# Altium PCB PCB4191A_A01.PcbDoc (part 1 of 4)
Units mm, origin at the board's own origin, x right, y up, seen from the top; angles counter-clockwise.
Board outline 160 x 160 mm, 6 copper layers (Top Layer, IM1 RIS, IM2 Signal, IM3 Signal, IM4 GND, Bottom Layer), stack 1.582 mm thick; 176 components, 121 nets, 494 pads, 4954 vias.
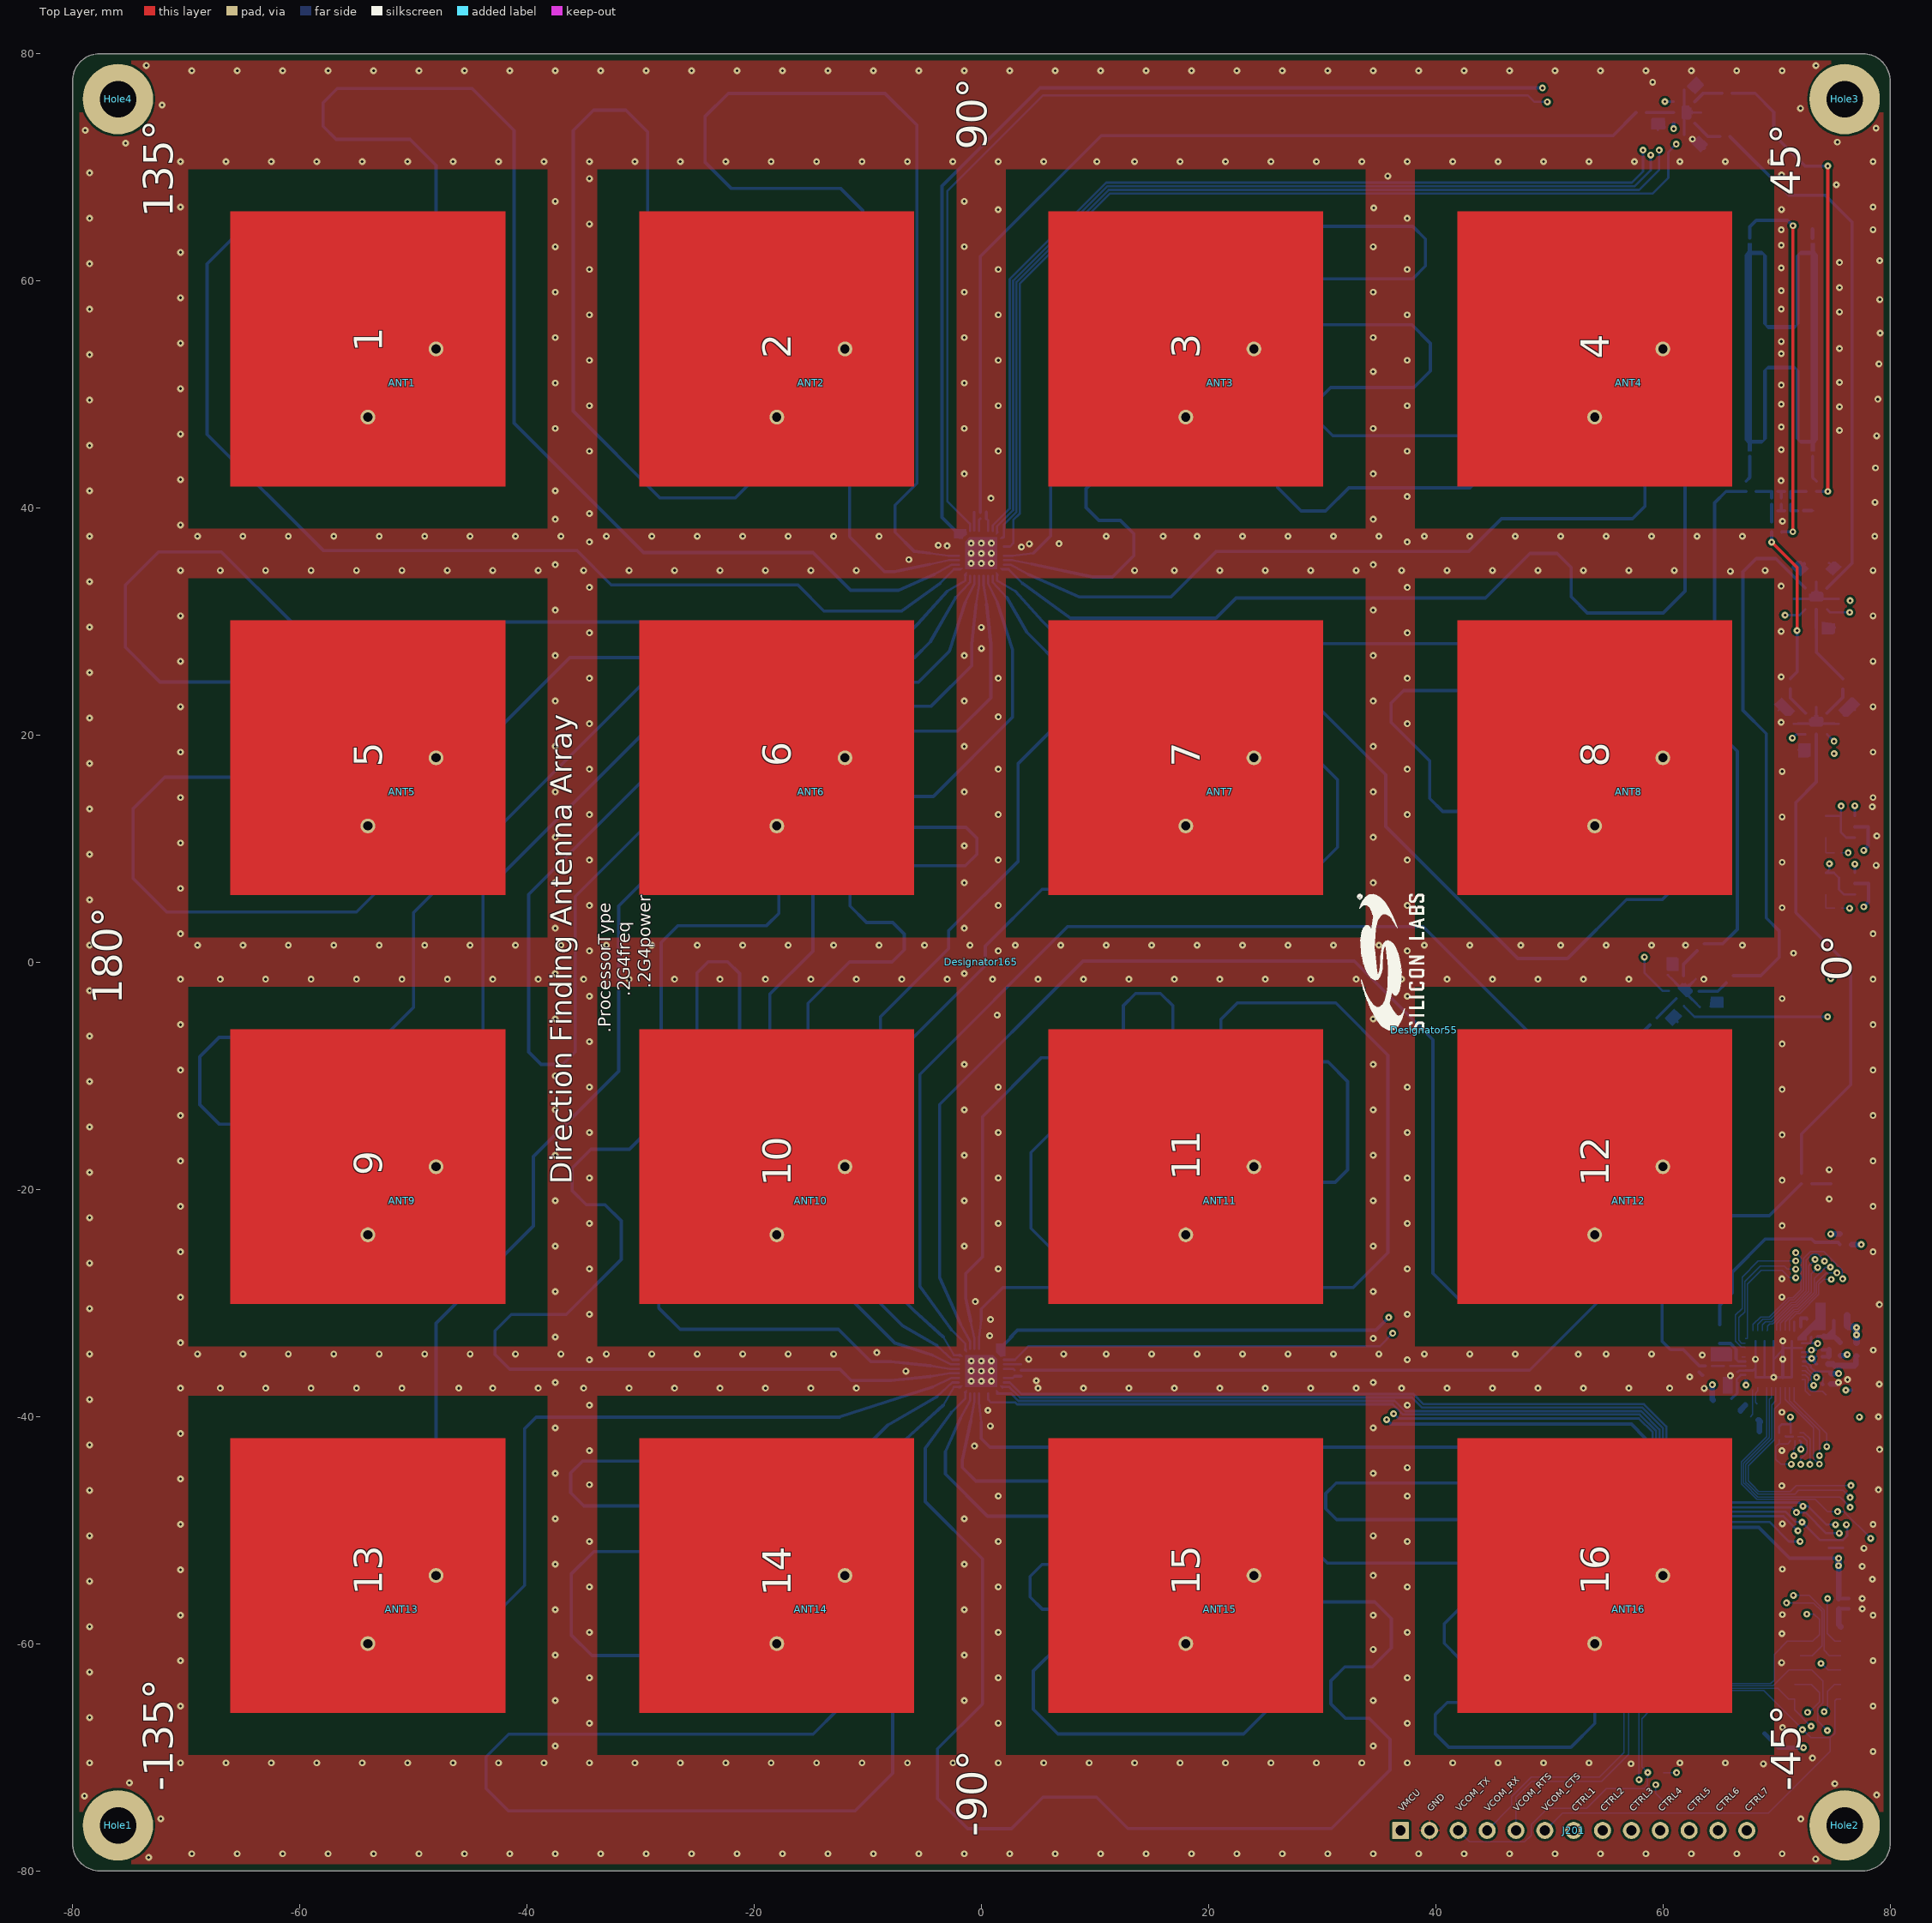
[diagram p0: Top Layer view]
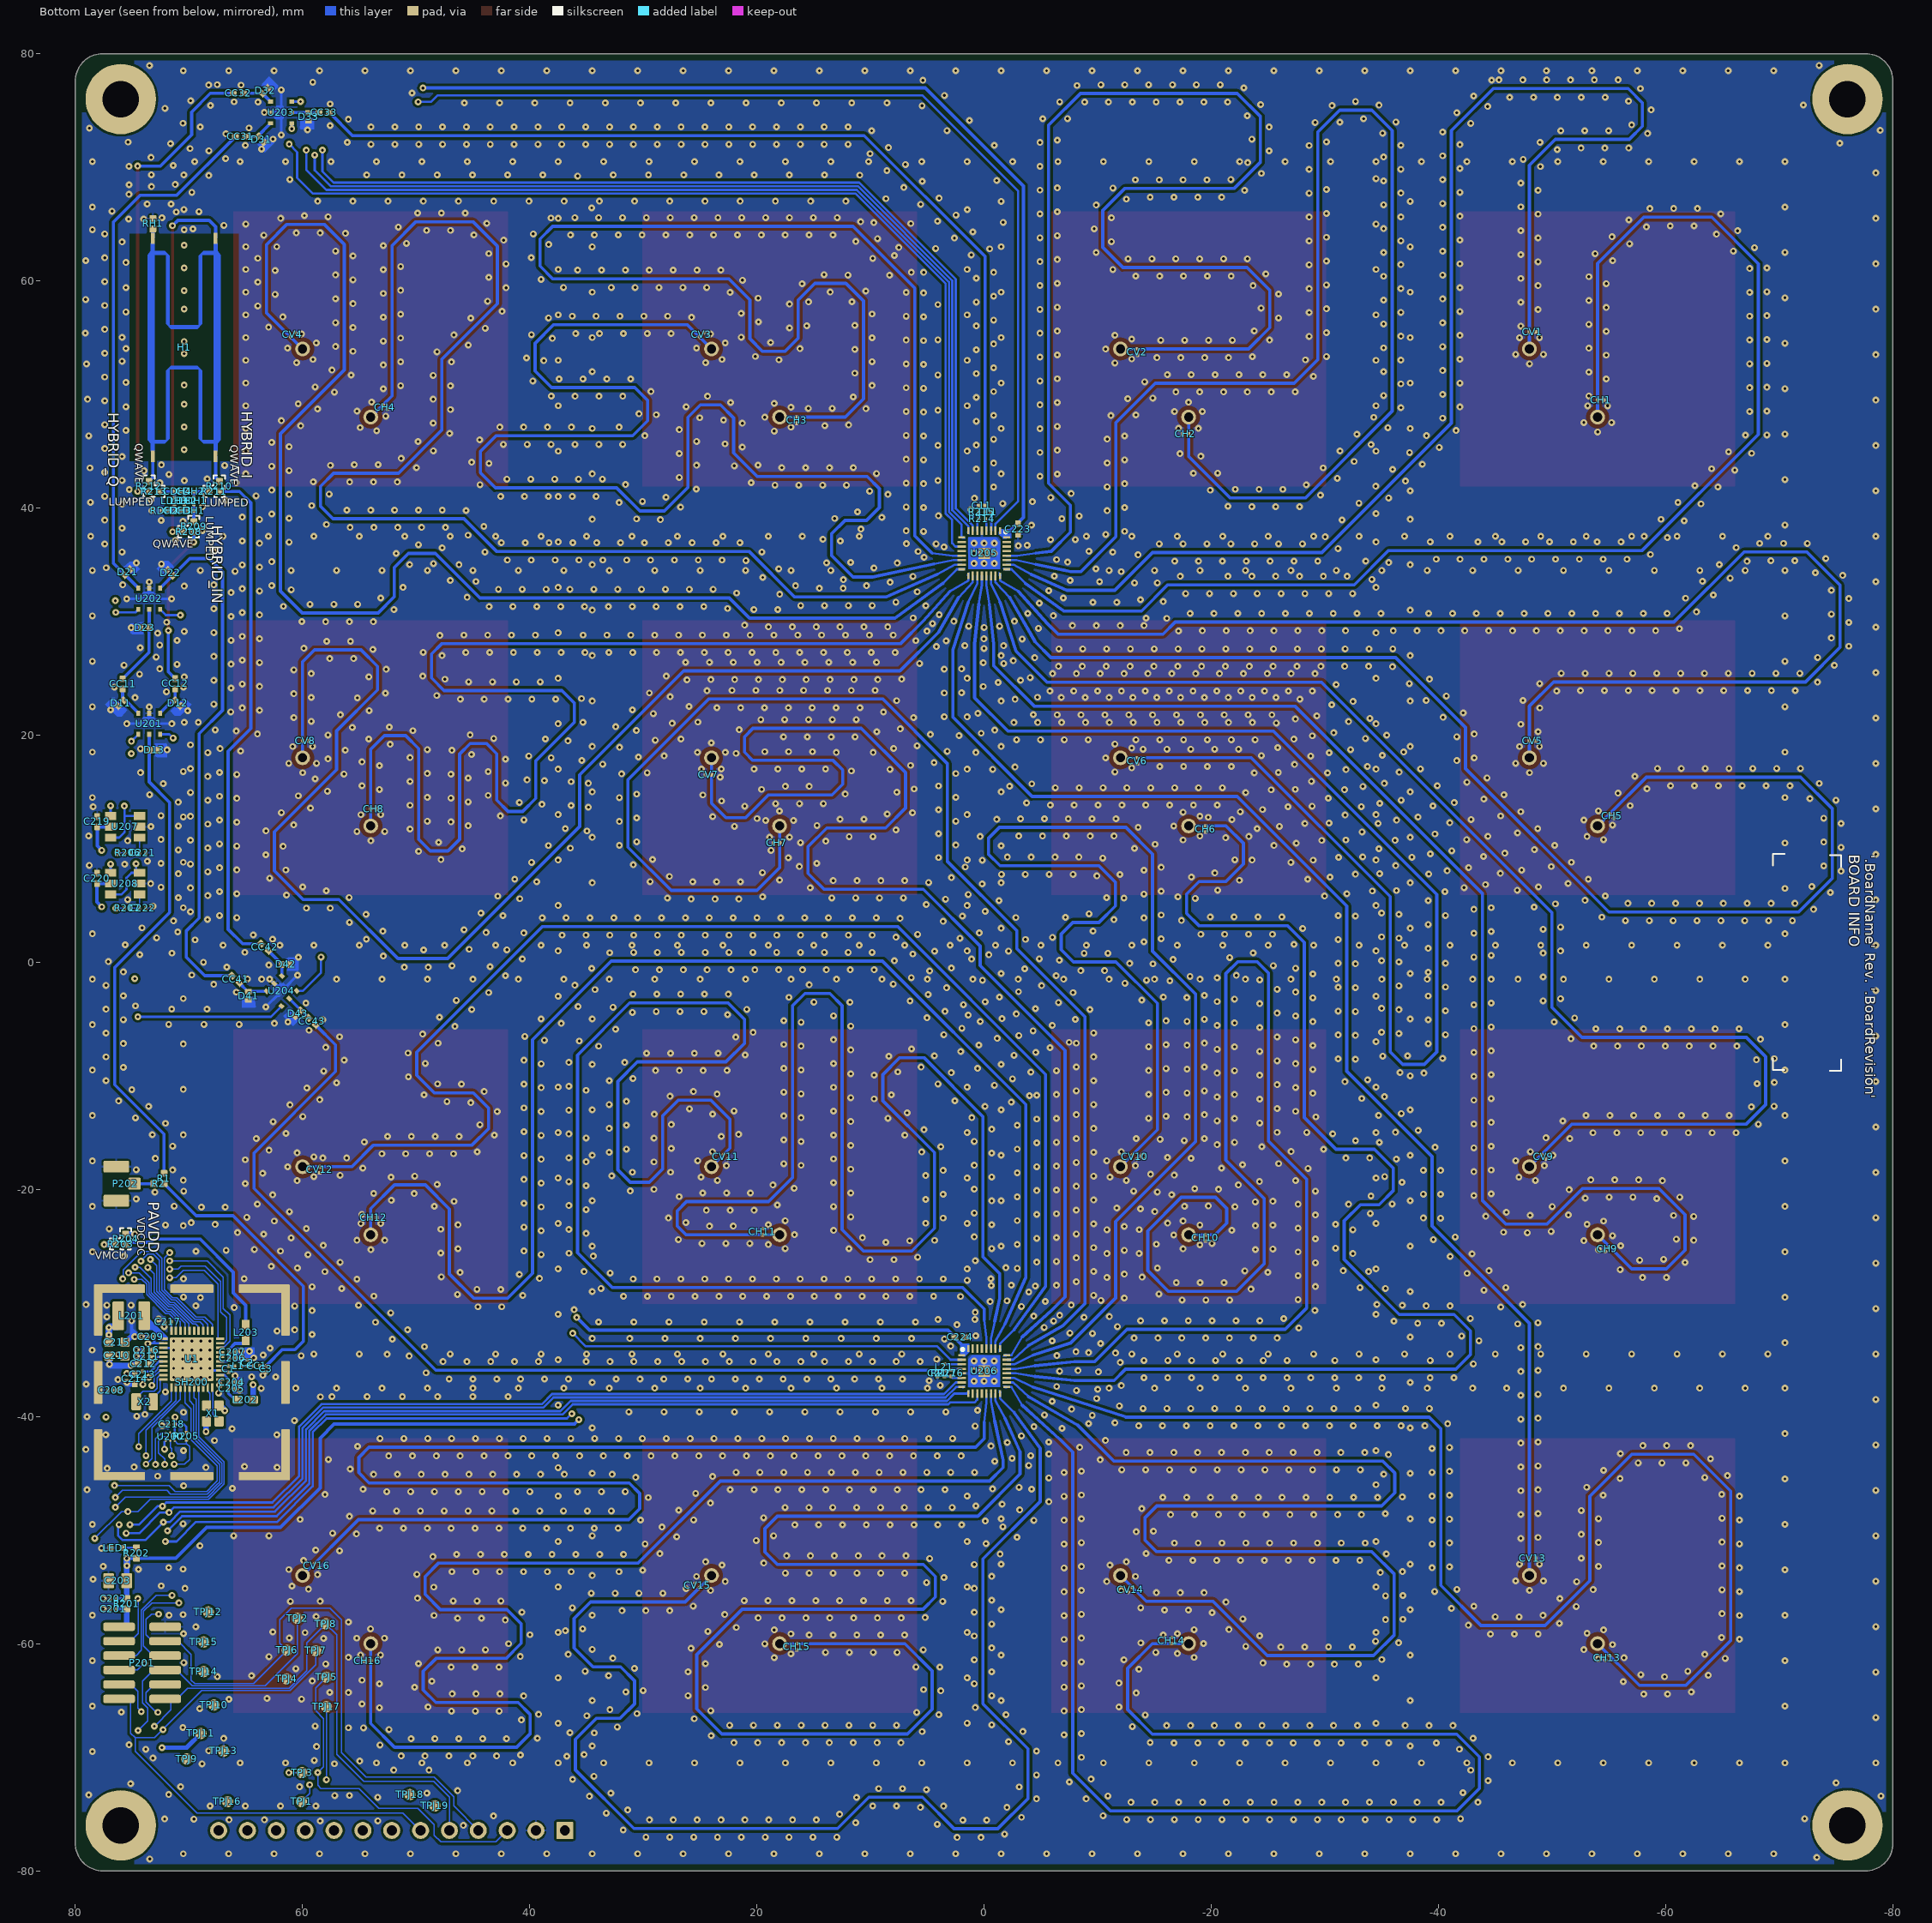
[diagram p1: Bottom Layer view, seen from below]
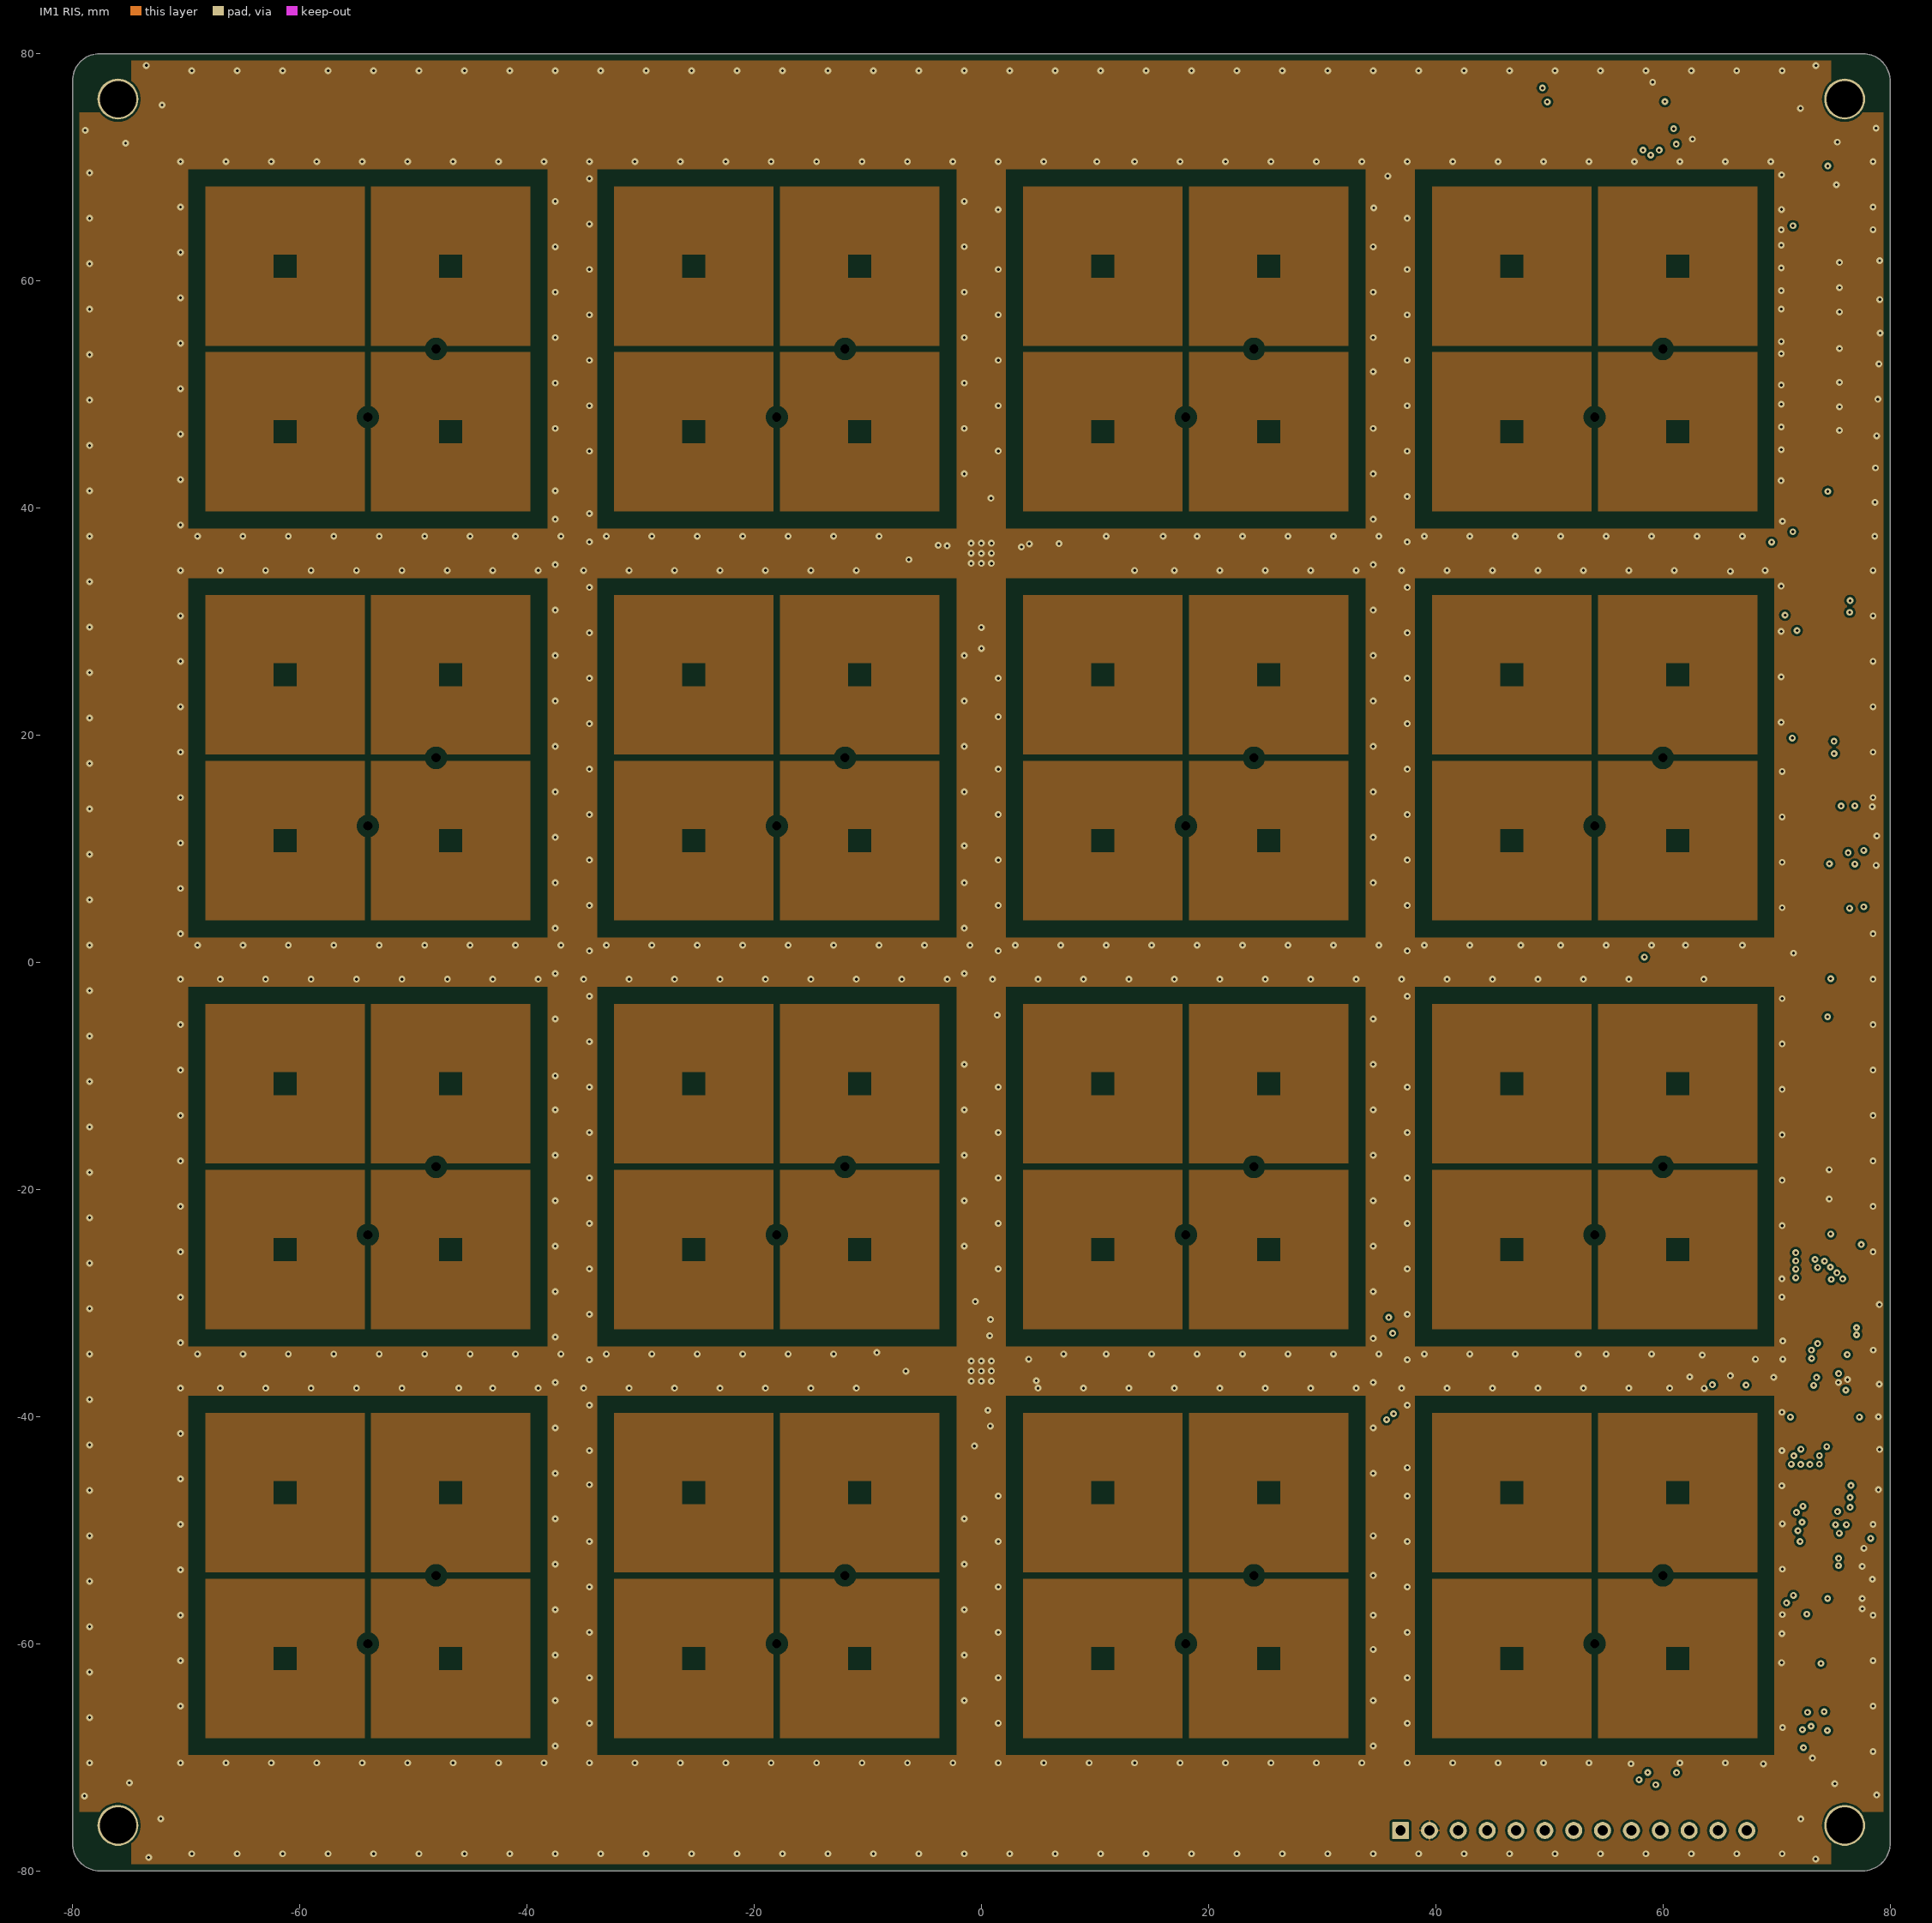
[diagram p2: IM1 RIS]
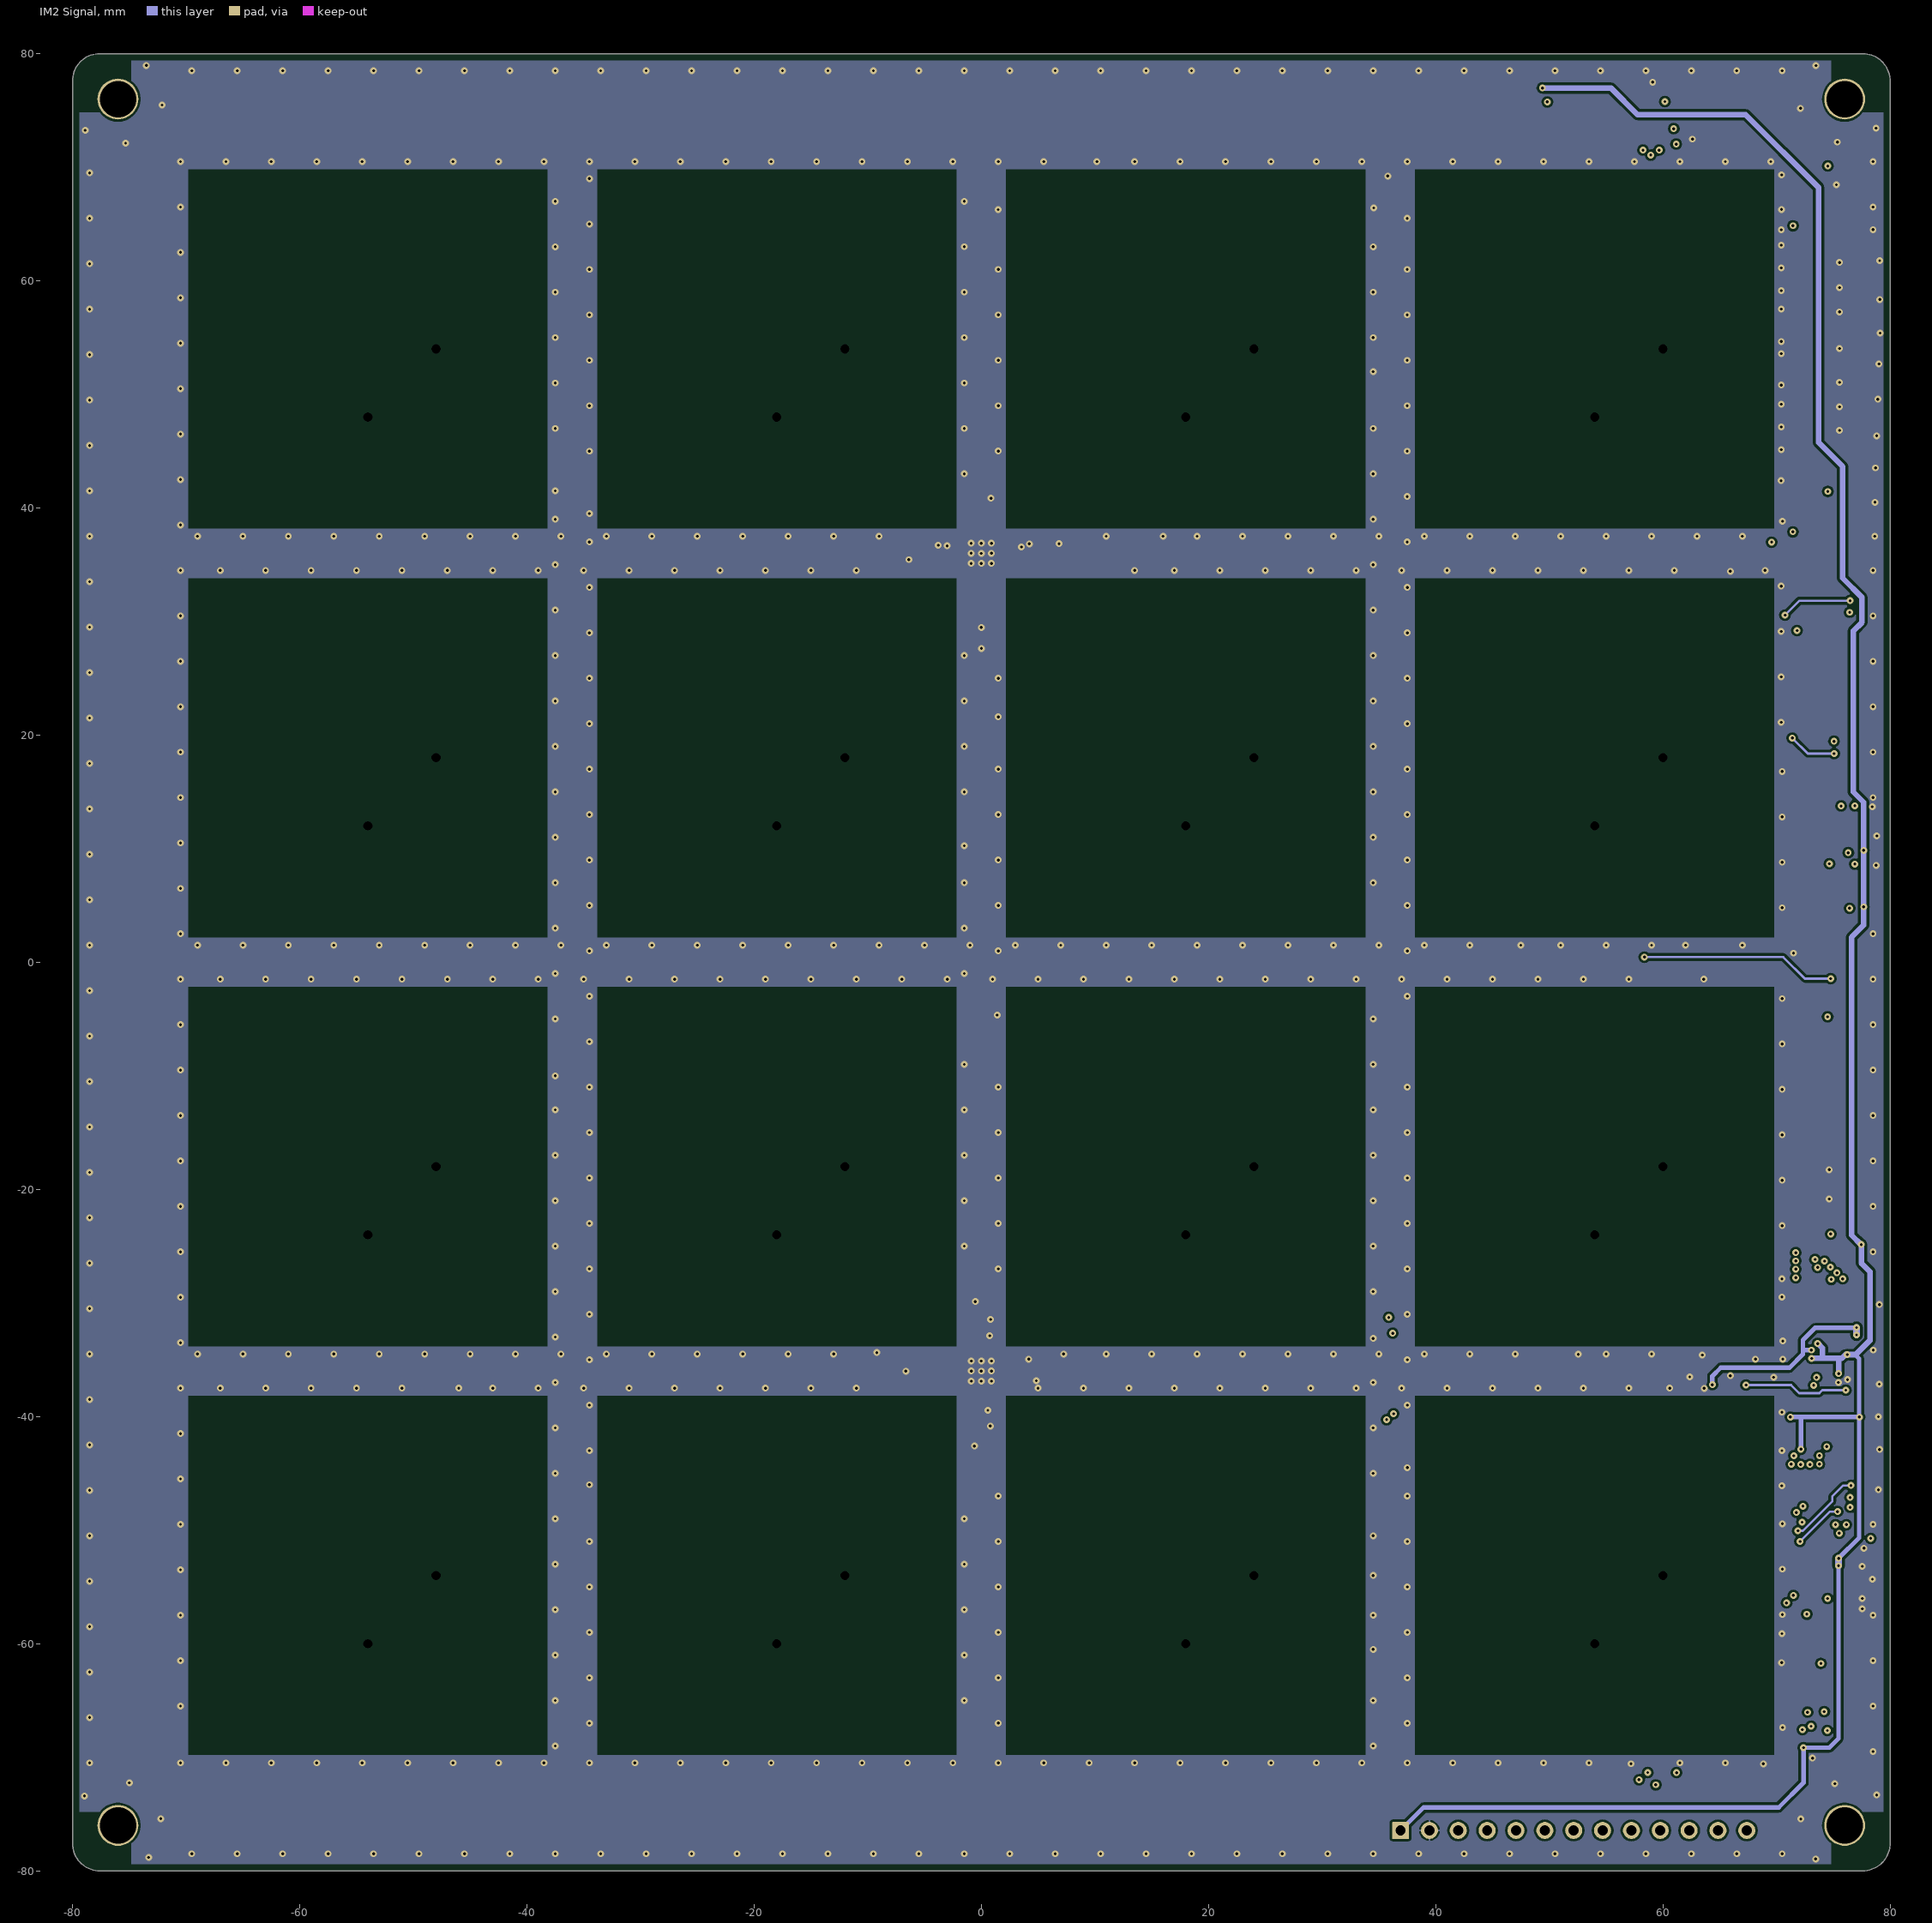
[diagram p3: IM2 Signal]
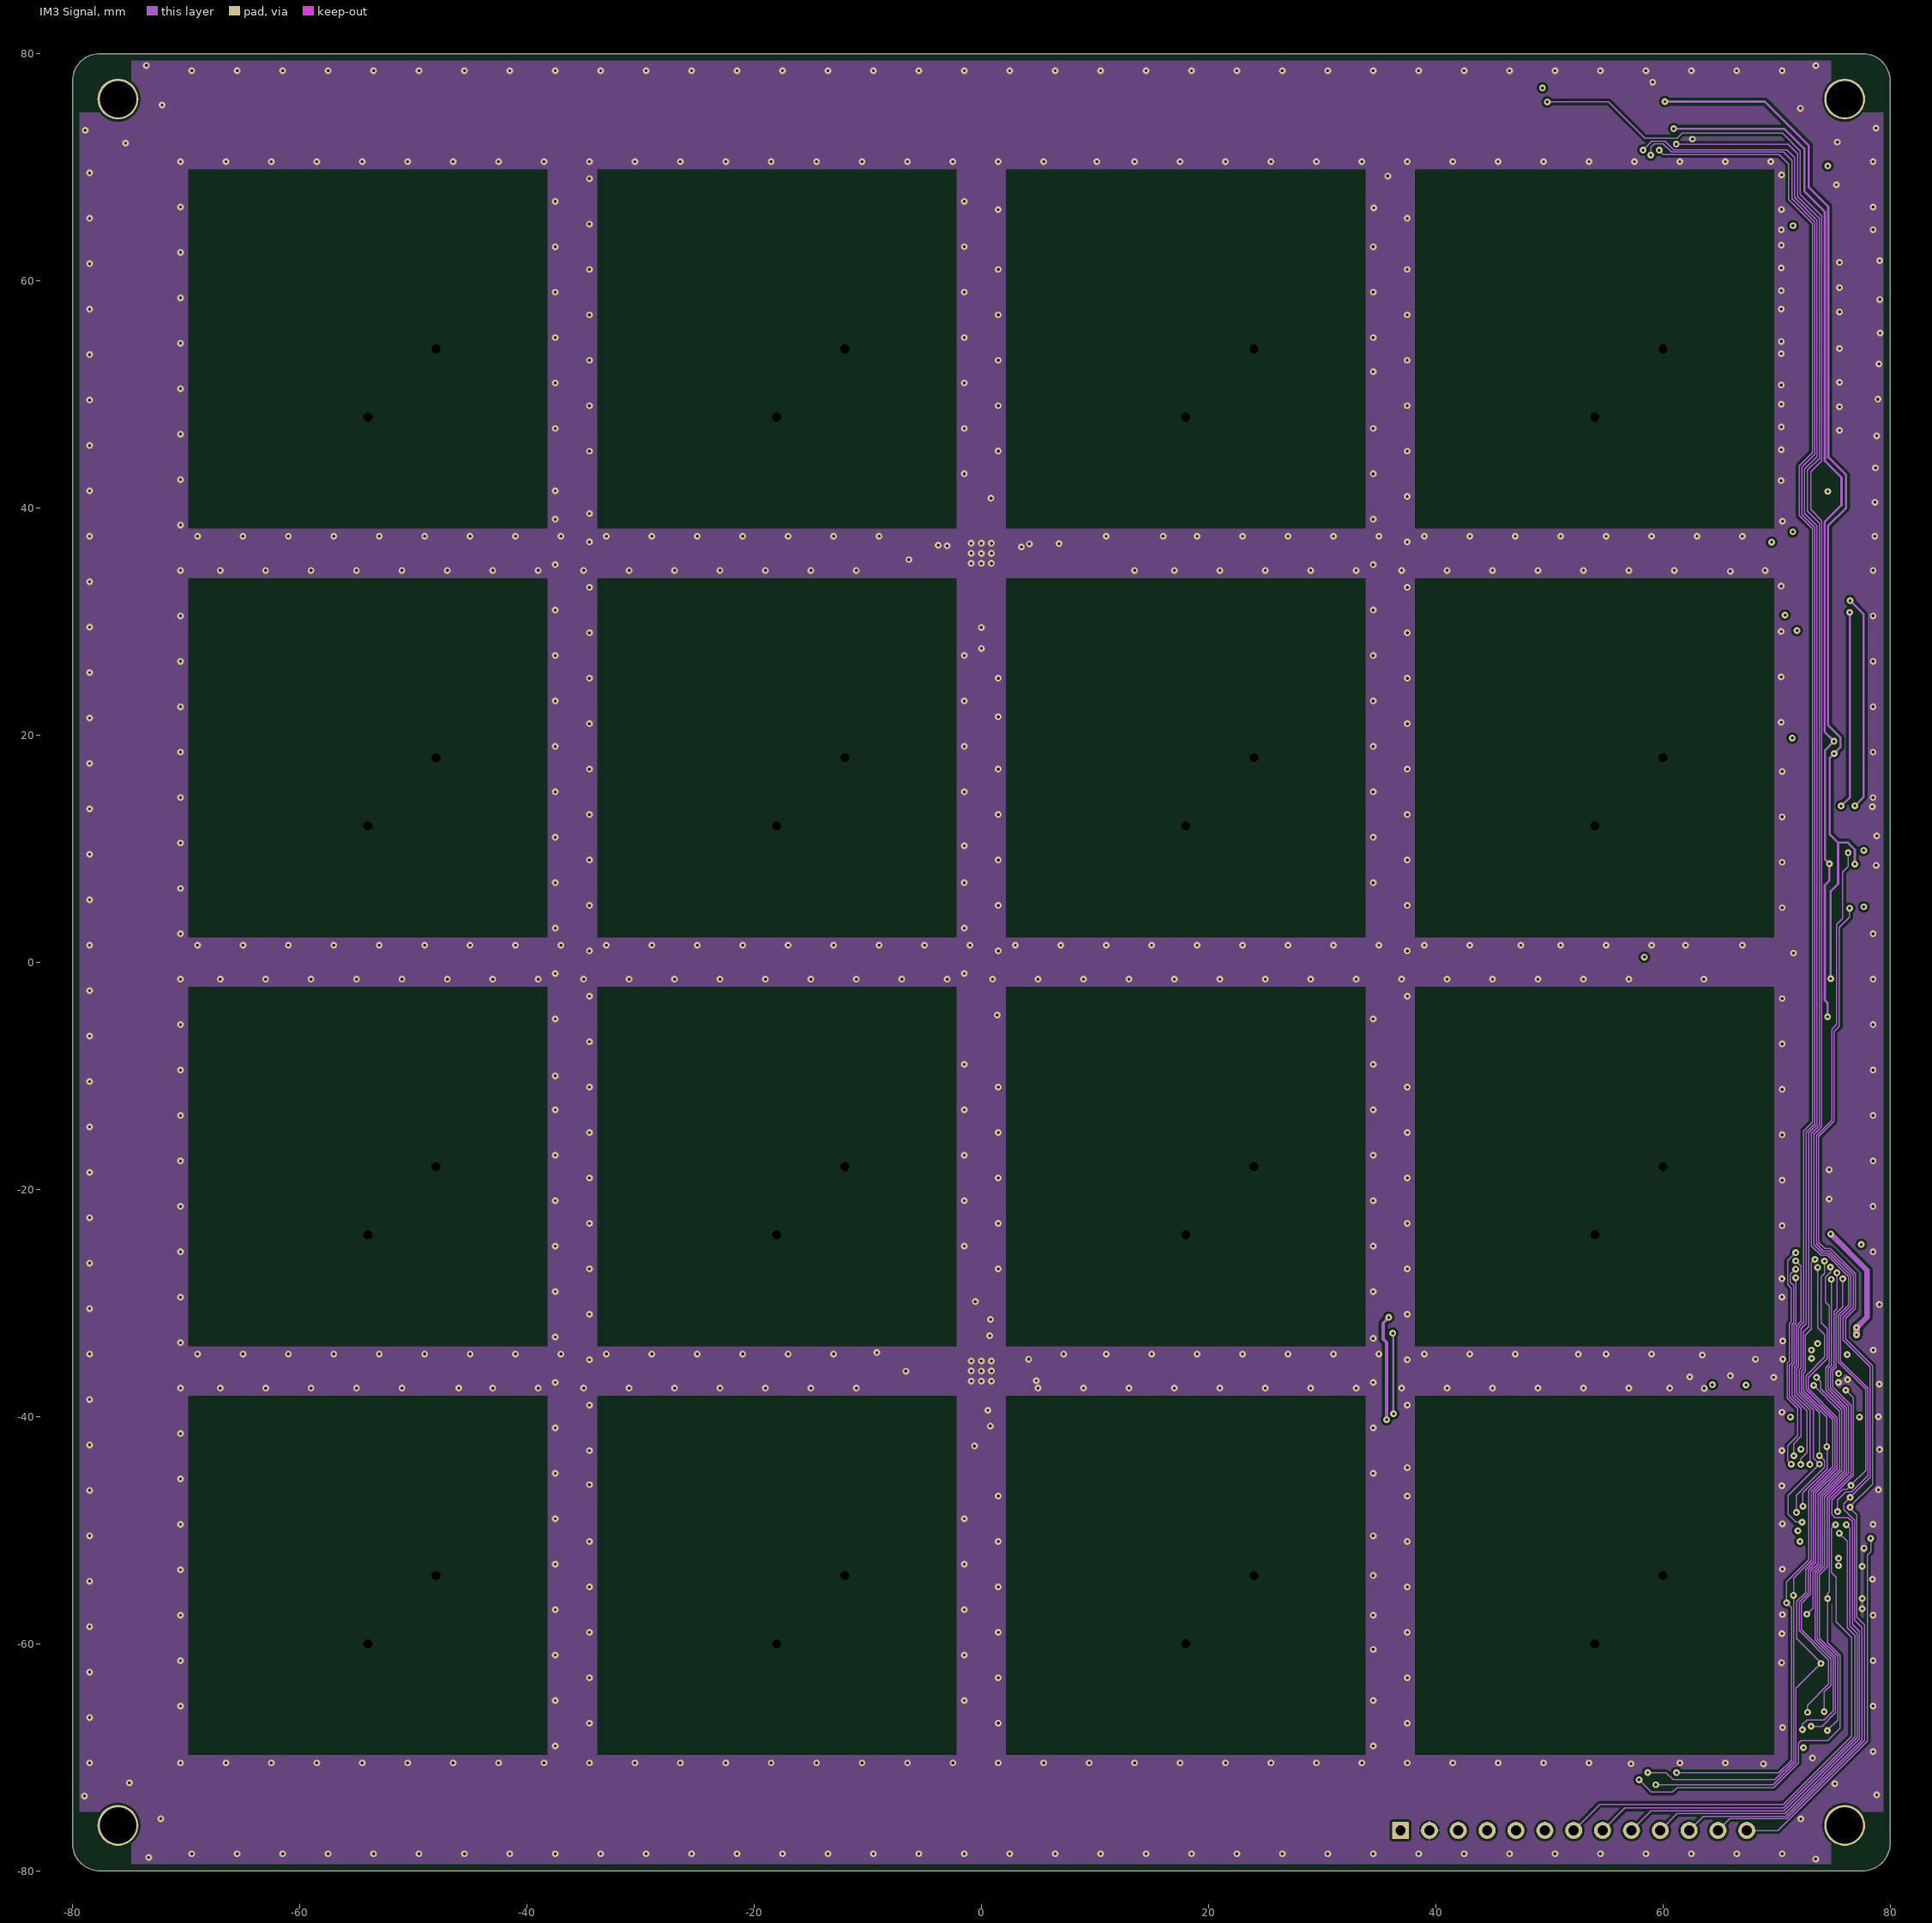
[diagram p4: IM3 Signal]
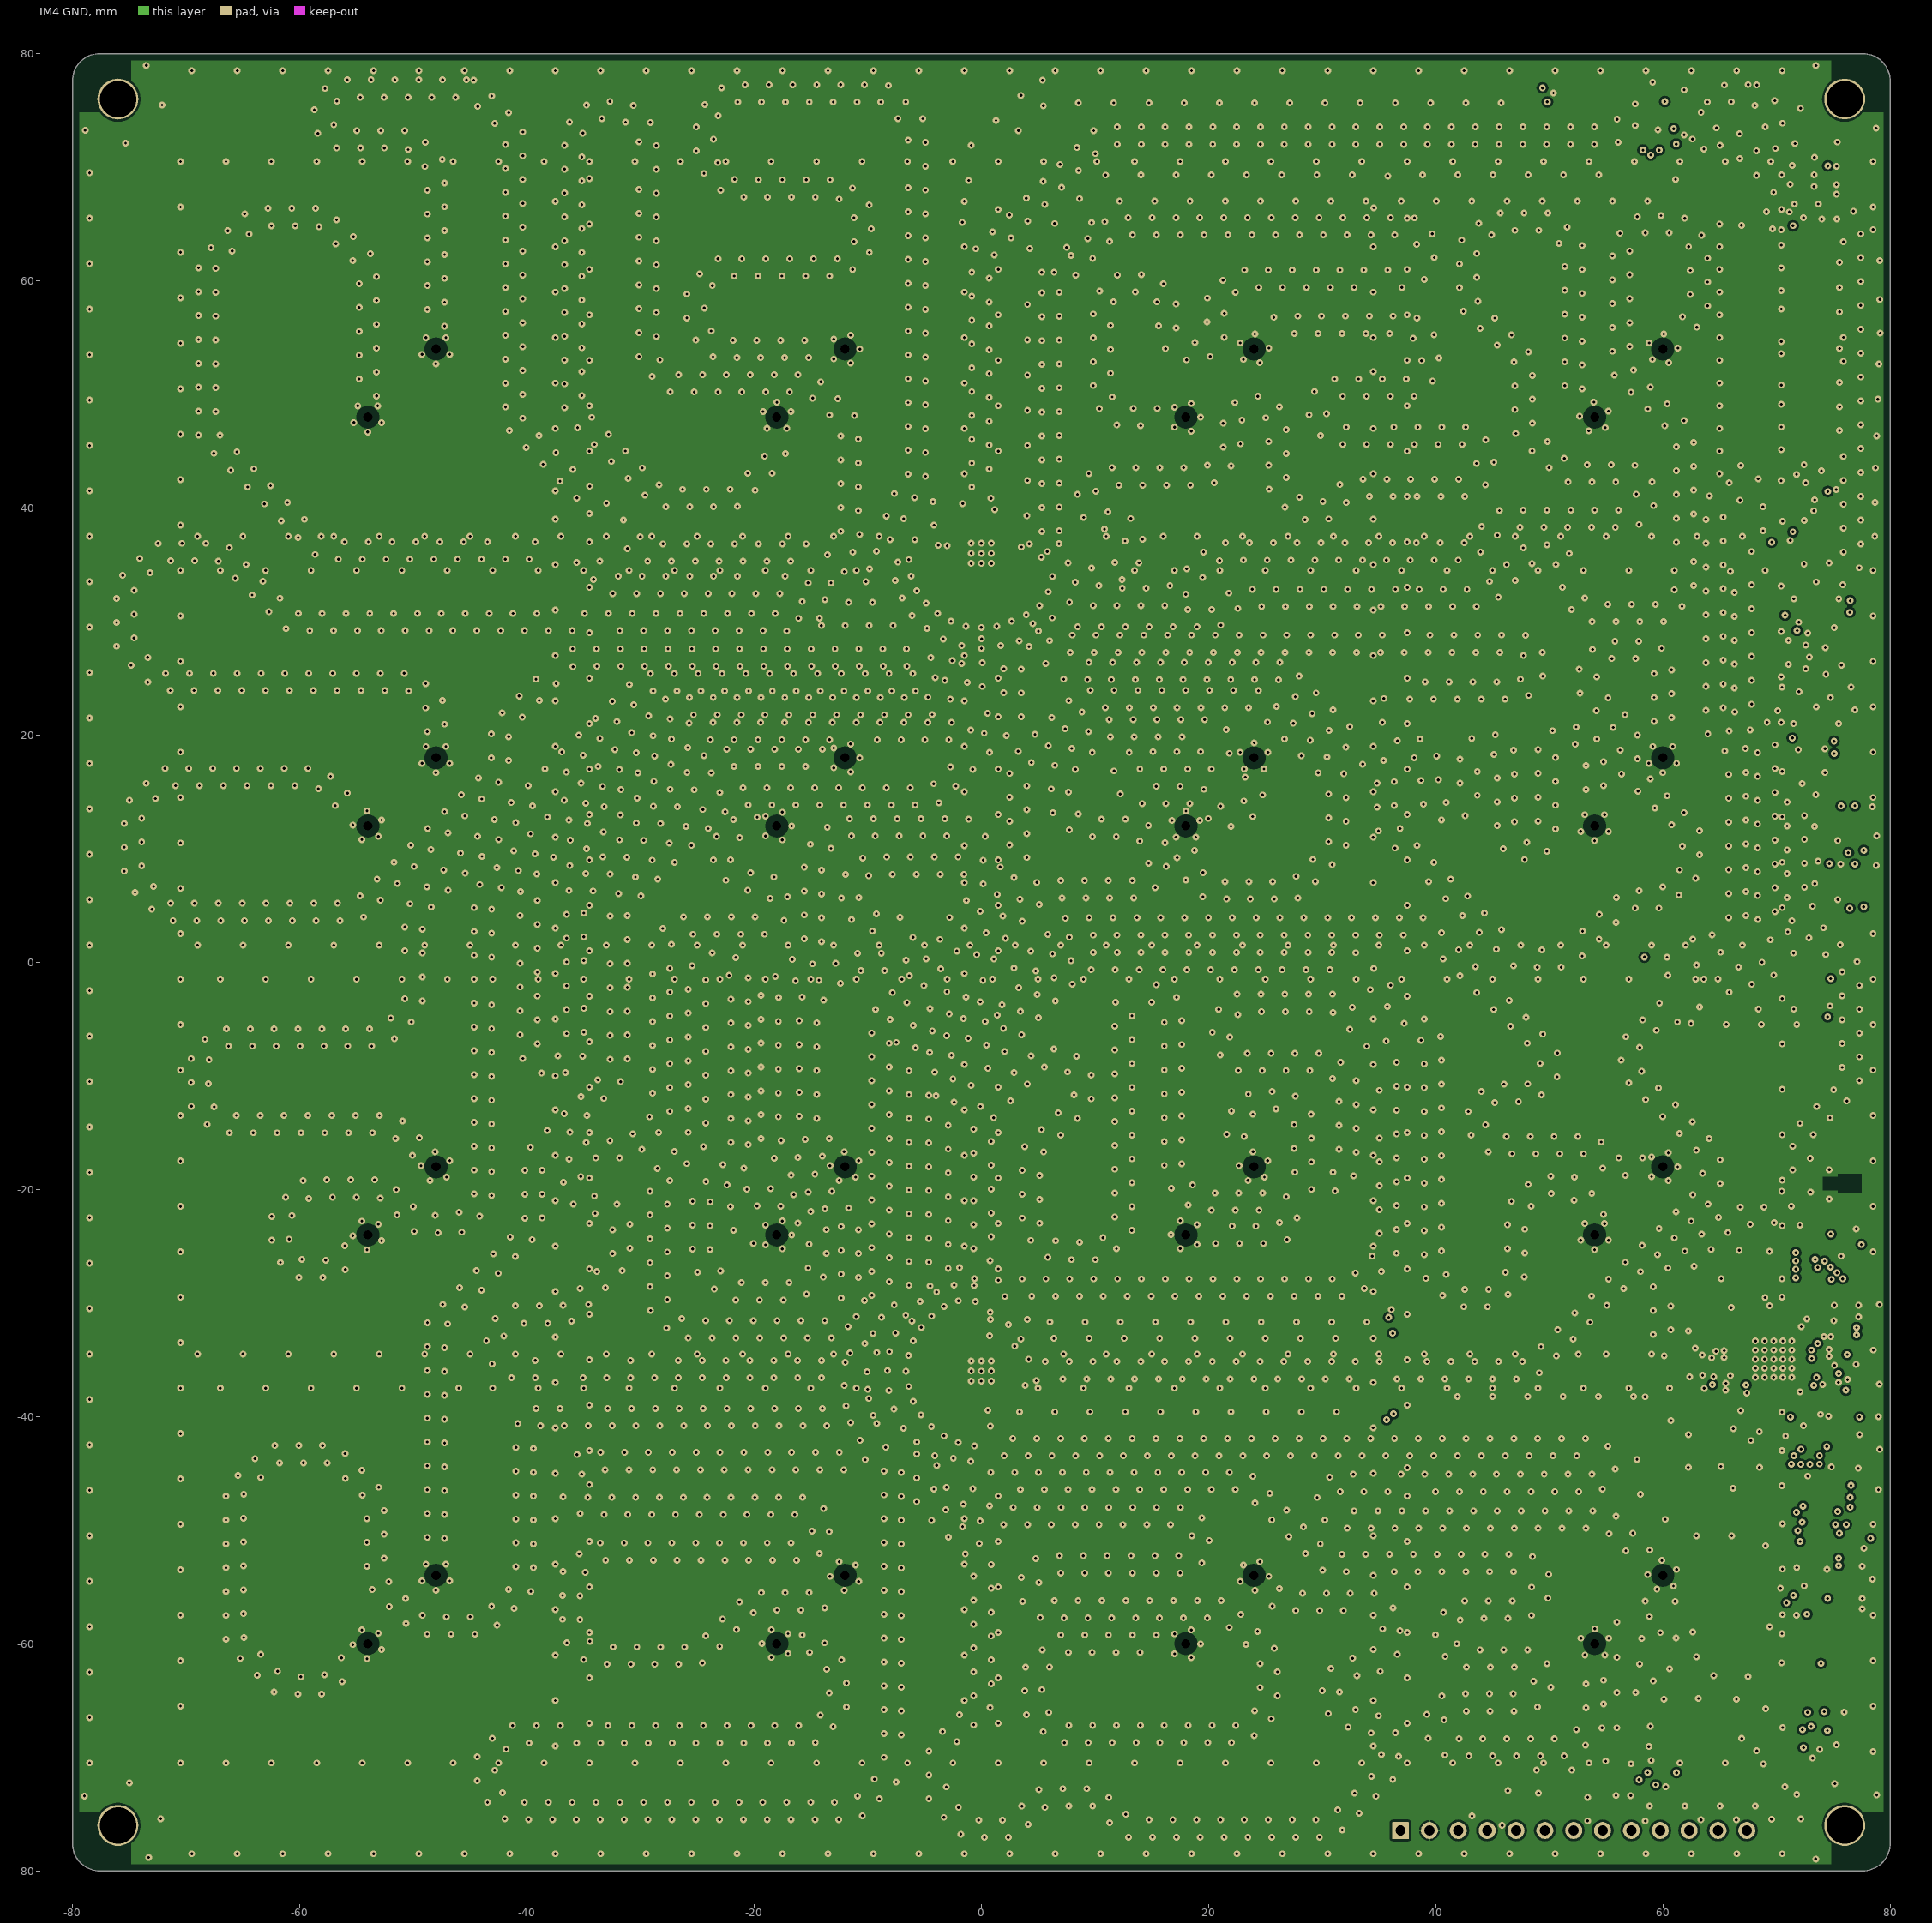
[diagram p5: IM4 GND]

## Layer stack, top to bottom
Top Solder: solder mask 0.0102, Solder Resist, Dk 3.5
Top Layer: signal copper 0.035
Dielectric 1: core 0.2, FR-4, Dk 4.4
IM1 RIS: signal copper 0.018
Dielectric 5: prepreg 0.42, Dk 4.2
IM2 Signal: signal copper 0.018
Dielectric 4: core 0.2, Dk 4.2
IM3 Signal: signal copper 0.018
Dielectric 3: prepreg 0.42, Dk 4.2
IM4 GND: signal copper 0.018
Dielectric 2: core 0.2, Dk 4.2
Bottom Layer: signal copper 0.035
Bottom Solder: solder mask 0.0102, Solder Resist, Dk 3.5

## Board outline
-80,-77.6 -80,77.6 cw(c-77.6,77.6) -77.6,80 77.6,80 cw(c77.6,77.6) 80,77.6 80,-77.6 cw(c77.6,-77.6) 77.6,-80 -77.6,-80 cw(c-77.6,-77.6)

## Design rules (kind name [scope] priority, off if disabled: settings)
AcuteAngle [All] p1: minimum=7.00000000000000E+0001 checktracksonly=FALSE
BoardOutlineClearance [All] p1: gap=0.6
Clearance Clearance_50Ohm [InNet('*ANT_*') vs InNet('GND')] p1: gap=0.2 except(0.23: Track-Poly)
Clearance Clearance_to_Holes [InPadClass('NPTH')] p2: gap=0.254
Clearance Clerance_Polygon [InPolygon] p3: gap=0.2 except(0.23: Track-Poly)
Clearance Clearance_General [All] p4: gap=0.1 except(0.23: Track-Poly)
HoleSize [All] p1: absolutevalues=TRUE maxlimit=5 minlimit=0.025 maxpercent=80.000 minpercent=20.000
HoleToHoleClearance HoleToHoleClearance_ANT1toPAD [Incomponent ('ANT1') vs ISpad] p1: gap=0 allowstackedmicrovias=TRUE
HoleToHoleClearance HoleToHoleClearance_R1toR2_1 [Incomponent ('R1') vs Incomponent ('R2')] p2: gap=0 allowstackedmicrovias=TRUE
HoleToHoleClearance HoleToHoleClearance_U1toVIA_1 [InComponent ('U1') vs IsVia] p3: gap=0 allowstackedmicrovias=TRUE
HoleToHoleClearance [All] p4: gap=0.254 allowstackedmicrovias=TRUE
MinimumSolderMaskSliver [All] p1: minsoldermaskwidth=0.102
PolygonConnect Polygon_VIA_Connect [IsVia] p1: connectstyle=Direct reliefconductorwidth=0.254 reliefentries=4 polygonreliefangle="90 Angle" airgapwidth=0.254
PolygonConnect PolygonConnect_SH100 [InComponent('SH200')] p2: connectstyle=Direct reliefconductorwidth=0.254 reliefentries=4 polygonreliefangle="90 Angle" airgapwidth=0.127
PolygonConnect PolygonConnect_RFMatching [InComponent('CH*') or InComponent('CV*')] p3: connectstyle=Direct reliefconductorwidth=0.254 reliefentries=4 polygonreliefangle="90 Angle" airgapwidth=0.127
PolygonConnect [All] p4: connectstyle=Relief reliefconductorwidth=0.2 reliefentries=4 polygonreliefangle="90 Angle" airgapwidth=0.15
RoutingVias [All] p1: holewidth=0.3 width=0.65 viastyle="Through Hole" minholewidth=0.25 minwidth=0.5 maxholewidth=1 maxwidth=1.5
ShortCircuit ShortCircuit_Hybrid [InComponent('H1') and InNet('HYBRID_*') vs InComponent('H1') or InNet('HYBRID_*')] p1: allowed=TRUE
ShortCircuit ShortCircuit_Antenna [Incomponent ('ANT*') vs Incomponent ('ANT*')] p2: allowed=TRUE
ShortCircuit [All] p3: allowed=FALSE
SilkToSilkClearance [All] p1: silktosilkclearance=0.102
SilkToSolderMaskClearance [IsPad] p1: minsilkscreentomaskgap=0.102 clearancetoexposedcopper=TRUE
SolderMaskExpansion [All] p1: expansion=0.051
Width 50ohm [InNet('50R*')] p1: maxlimit=0.3 minlimit=0.1 preferedwidth=0.28
Width [All] p2: maxlimit=5.08 minlimit=0.1 preferedwidth=0.125
24 further rules are at their usual default settings.

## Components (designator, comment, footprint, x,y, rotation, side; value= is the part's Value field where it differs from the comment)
ANT1 "RECT_DP_PATCH_6LAYER_4x4_RIS" 6LAYER_RECT_DP_PATCH_24mm2_14mmRIS_31mm6CELL_6mm1FP -54,54 r270 top
ANT2 "RECT_DP_PATCH_6LAYER_4x4_RIS" 6LAYER_RECT_DP_PATCH_24mm2_14mmRIS_31mm6CELL_6mm1FP -18,54 r270 top
ANT3 "RECT_DP_PATCH_6LAYER_4x4_RIS" 6LAYER_RECT_DP_PATCH_24mm2_14mmRIS_31mm6CELL_6mm1FP 18,54 r270 top
ANT4 "RECT_DP_PATCH_6LAYER_4x4_RIS" 6LAYER_RECT_DP_PATCH_24mm2_14mmRIS_31mm6CELL_6mm1FP 54,54 r270 top
ANT5 "RECT_DP_PATCH_6LAYER_4x4_RIS" 6LAYER_RECT_DP_PATCH_24mm2_14mmRIS_31mm6CELL_6mm1FP -54,18 r270 top
ANT6 "RECT_DP_PATCH_6LAYER_4x4_RIS" 6LAYER_RECT_DP_PATCH_24mm2_14mmRIS_31mm6CELL_6mm1FP -18,18 r270 top
ANT7 "RECT_DP_PATCH_6LAYER_4x4_RIS" 6LAYER_RECT_DP_PATCH_24mm2_14mmRIS_31mm6CELL_6mm1FP 18,18 r270 top
ANT8 "RECT_DP_PATCH_6LAYER_4x4_RIS" 6LAYER_RECT_DP_PATCH_24mm2_14mmRIS_31mm6CELL_6mm1FP 54,18 r270 top
ANT9 "RECT_DP_PATCH_6LAYER_4x4_RIS" 6LAYER_RECT_DP_PATCH_24mm2_14mmRIS_31mm6CELL_6mm1FP -54,-18 r270 top
ANT10 "RECT_DP_PATCH_6LAYER_4x4_RIS" 6LAYER_RECT_DP_PATCH_24mm2_14mmRIS_31mm6CELL_6mm1FP -18,-18 r270 top
ANT11 "RECT_DP_PATCH_6LAYER_4x4_RIS" 6LAYER_RECT_DP_PATCH_24mm2_14mmRIS_31mm6CELL_6mm1FP 18,-18 r270 top
ANT12 "RECT_DP_PATCH_6LAYER_4x4_RIS" 6LAYER_RECT_DP_PATCH_24mm2_14mmRIS_31mm6CELL_6mm1FP 54,-18 r270 top
ANT13 "RECT_DP_PATCH_6LAYER_4x4_RIS" 6LAYER_RECT_DP_PATCH_24mm2_14mmRIS_31mm6CELL_6mm1FP -54,-54 r270 top
ANT14 "RECT_DP_PATCH_6LAYER_4x4_RIS" 6LAYER_RECT_DP_PATCH_24mm2_14mmRIS_31mm6CELL_6mm1FP -18,-54 r270 top
ANT15 "RECT_DP_PATCH_6LAYER_4x4_RIS" 6LAYER_RECT_DP_PATCH_24mm2_14mmRIS_31mm6CELL_6mm1FP 18,-54 r270 top
ANT16 "RECT_DP_PATCH_6LAYER_4x4_RIS" 6LAYER_RECT_DP_PATCH_24mm2_14mmRIS_31mm6CELL_6mm1FP 54,-54 r270 top
C1 "1P2" C0201_L 66.5,-35.825 r270 bottom
C2 "1P3" C0201_L 64.85,-35.281 r90 bottom
C3 "TBD" C0201_L 63.2,-35.825 r270 bottom
C11 "1P0" C0201_L 0.209,40.218 r180 bottom
C21 "1P0" C0201_L 4.111,-36.199 r90 bottom
C201 "100N" C0201_L 76.65,-56.937 r0 bottom
C202 "100N" C0201_L 76.65,-56.037 r0 bottom
C203 "10U" C0805_L 76.275,-54.462 r0 bottom
C204 "120P" C0201_L 66.25,-37 r180 bottom
C205 "100N" C0201_L 66.25,-37.55 r180 bottom
C206 "120P" C0201_L 66.175,-34.881 r180 bottom
C207 "100N" C0201_L 66.175,-34.331 r180 bottom
C208 "100N" C0201_L 76.852,-37.686 r0 bottom
C209 "100N" C0201_L 73.35,-32.981 r0 bottom
C210 "10U" C0603_L 76.35,-34.656 r0 bottom
C211 "10N" C0201_L 73.75,-34.725 r0 bottom
C212 "1U" C0402_L 74.025,-35.375 r0 bottom
C213 "100N" C0201_L 74.1,-36.306 r270 bottom
C214 "1U" C0402_L 74.775,-36.681 r270 bottom
C215 "4U7" C0603_L 76.35,-33.456 r180 bottom
C216 "100N" C0201_L 73.75,-34.15 r0 bottom
C217 "1U" C0201_L 71.85,-31.675 r0 bottom
C218 "100N" C0201_L 71.525,-40.675 r0 bottom
C219 "100N" C0402_L 78.078,12.371 r270 bottom
C220 "100N" C0402_L 78.097,7.378 r270 bottom
C221 "TBD" C0201_L 74.08,9.639 r0 bottom
C222 "TBD" C0201_L 74.079,4.759 r0 bottom
C223 "100N" C0402_L -2.987,38.141 r90 bottom
C224 "100N" C0402_L 2.113,-33.009 r0 bottom
CC1 "18P" C0201_L 64.025,-35.55 r180 bottom
CC11 "12P" C0402_L 75.838,24.504 r270 bottom
CC12 "12P" C0402_L 71.212,24.524 r270 bottom
CC31 "12P" C0402_L 65.47,72.692 r0 bottom
CC32 "12P" C0402_L 65.656,76.507 r0 bottom
CC33 "12P" C0402_L 58.101,74.825 r0 bottom
CC41 "12P" C0402_L 65.886,-1.507 r45 bottom
CC42 "12P" C0402_L 63.32,1.322 r45 bottom
CC43 "12P" C0402_L 59.168,-5.21 r45 bottom
CDH1 "1P1" C0201_L 69.842,39.753 r0 bottom
CDH2 "1P1" C0201_L 69.842,41.453 r0 bottom
CDH3 "1P1" C0201_L 70.992,39.753 r0 bottom
CDH4 "1P1" C0201_L 70.992,41.453 r0 bottom
CH1 "TBD" C0201_NOPASTE -54.275,49.5 r180 bottom
CH2 "TBD" C0201_NOPASTE -17.725,46.5 r0 bottom
CH3 "TBD" C0201_NOPASTE 16.5,47.725 r270 bottom
CH4 "TBD" C0201_NOPASTE 52.745,48.866 r225 bottom
CH5 "TBD" C0201_NOPASTE -55.255,12.866 r225 bottom
CH6 "TBD" C0201_NOPASTE -19.5,11.725 r270 bottom
CH7 "TBD" C0201_NOPASTE 18.275,10.5 r0 bottom
CH8 "TBD" C0201_NOPASTE 53.725,13.5 r180 bottom
CH9 "TBD" C0201_NOPASTE -54.866,-25.255 r315 bottom
CH10 "TBD" C0201_NOPASTE -19.5,-24.275 r270 bottom
CH11 "TBD" C0201_NOPASTE 19.5,-23.725 r90 bottom
CH12 "TBD" C0201_NOPASTE 53.725,-22.5 r180 bottom
CH13 "TBD" C0201_NOPASTE -54.866,-61.255 r315 bottom
CH14 "TBD" C0201_NOPASTE -16.5,-59.725 r90 bottom
CH15 "TBD" C0201_NOPASTE 16.5,-60.275 r270 bottom
CH16 "TBD" C0201_NOPASTE 54.275,-61.5 r0 bottom
CV1 "TBD" C0201_NOPASTE -48.275,55.5 r180 bottom
CV2 "TBD" C0201_NOPASTE -13.5,53.725 r270 bottom
CV3 "TBD" C0201_NOPASTE 24.866,55.255 r135 bottom
CV4 "TBD" C0201_NOPASTE 60.866,55.255 r135 bottom
CV5 "TBD" C0201_NOPASTE -48.275,19.5 r180 bottom
CV6 "TBD" C0201_NOPASTE -13.5,17.725 r270 bottom
CV7 "TBD" C0201_NOPASTE 24.275,16.5 r0 bottom
CV8 "TBD" C0201_NOPASTE 59.725,19.5 r180 bottom
CV9 "TBD" C0201_NOPASTE -49.255,-17.134 r225 bottom
CV10 "TBD" C0201_NOPASTE -13.255,-17.134 r225 bottom
CV11 "TBD" C0201_NOPASTE 22.745,-17.134 r225 bottom
CV12 "TBD" C0201_NOPASTE 58.5,-18.275 r270 bottom
CV13 "TBD" C0201_NOPASTE -48.275,-52.5 r180 bottom
CV14 "TBD" C0201_NOPASTE -12.866,-55.255 r315 bottom
CV15 "TBD" C0201_NOPASTE 25.255,-54.866 r45 bottom
CV16 "TBD" C0201_NOPASTE 58.745,-53.134 r225 bottom
D11 "ESD7551" X2DFN2_1.0x0.6_0.65P 76,22.8 r135 bottom
D12 "ESD7551" X2DFN2_1.0x0.6_0.65P 71,22.8 r45 bottom
D13 "ESD7551" X2DFN2_1.0x0.6_0.65P 73.075,18.675 r0 bottom
D21 "ESD7551" X2DFN2_1.0x0.6_0.65P 75.424,34.355 r315 bottom
D22 "ESD7551" X2DFN2_1.0x0.6_0.65P 71.648,34.284 r225 bottom
D23 "ESD7551" X2DFN2_1.0x0.6_0.65P 73.889,29.455 r180 bottom
D31 "ESD7551" X2DFN2_1.0x0.6_0.65P 63.648,72.456 r45 bottom
D32 "ESD7551" X2DFN2_1.0x0.6_0.65P 63.291,76.738 r315 bottom
D33 "ESD7551" X2DFN2_1.0x0.6_0.65P 59.476,74.436 r90 bottom
D41 "ESD7551" X2DFN2_1.0x0.6_0.65P 64.765,-2.963 r90 bottom
D42 "ESD7551" X2DFN2_1.0x0.6_0.65P 61.485,-0.188 r0 bottom
D43 "ESD7551" X2DFN2_1.0x0.6_0.65P 60.415,-4.513 r135 bottom
Designator55 "Comment" LOGO_SILABS_W12.0 39,-6 r90 top
Designator165 "Comment" PCB_ASSEMBLY_FRAME_A3 0,0 r0 top locked
Designator167 "Comment" PCB_SPEC_6_LAYER_BLINDVIA -91,310 r0 top
H1 "90DEG_HYBRID_6LAYER" 90DEG_HYBRID_EUROCIRCUITS_6LAYER_0mm2 70.42,54.146 r270 bottom net-tie
Hole1 "Comment" 3MM_PLATED -76,-76 r0 top
Hole2 "Comment" 3MM_PLATED 76,-76 r0 top
Hole3 "Comment" 3MM_PLATED 76,76 r0 top
Hole4 "Comment" 3MM_PLATED -76,76 r0 top
J201 "1X13 2.54MM" HEADER_1X13_2.54MM_TH 52.15,-76.45 r0 top
L1 "2N6" COIL_0201_L 65.675,-35.55 r180 bottom
L11 "2N0" R0201_L#1 -0.337,39.625 r180 bottom
L21 "2N0" R0201_L#1 3.497,-35.656 r90 bottom
L201 "2U2" COIL_1008_L 75.082,-31.125 r0 bottom
L202 "BLM18AG102SN1" COIL_MUR_BLM18_0603 65.05,-38.525 r0 bottom
L203 "BLM18AG102SN1" COIL_MUR_BLM18_0603 65,-32.6 r270 bottom
LDH1 "3N3" COIL_0201_L 69.567,40.603 r90 bottom
LDH2 "3N3" COIL_0201_L 70.417,40.603 r90 bottom
LDH3 "3N3" COIL_0201_L 71.267,40.603 r90 bottom
LED1 "GREEN" LED0402_L 76.375,-51.575 r180 bottom
P201 "HEADER_2X6_1.27MM_SMD" FTSH_106_01_L_DV_K 74.125,-61.687 r270 bottom
P202 "U.FL" COAX_HIROSE_U.FL_CL331-0471 76.395,-19.497 r270 bottom
R1 "0R" R0402_L 72.195,-19.047 r90 bottom
R2 "0R" R0402_L 72.645,-19.497 r0 bottom
R201 "0R" R0402_L 75.475,-56.487 r90 bottom
R202 "1K96" R0402_L 74.625,-52.025 r90 bottom
R203 "0R" R0402_L 76.021,-24.833 r0 bottom
R204 "0R" R0402_L 75.575,-24.375 r270 bottom
R205 "330K" R0201_L#2 70.225,-41.725 r90 bottom
R206 "0R" R0201_L#1 75.38,9.639 r180 bottom
R207 "0R" R0201_L#1 75.419,4.76 r180 bottom
R208 "0R" R0402_L 70.017,37.889 r0 bottom
R209 "0R" R0402_L 69.567,38.339 r270 bottom
R210 "0R" R0402_L 67.32,41.9 r270 bottom
R211 "0R" R0402_L 67.77,41.45 r180 bottom
R212 "0R" R0402_L 73.52,41.9 r270 bottom
R213 "0R" R0402_L 73.07,41.45 r0 bottom
R214 "0R" R0201_L#1 0.188,39.05 r180 bottom
R215 "0R" R0201_L#1 0.213,39.625 r0 bottom
R216 "0R" R0201_L#1 2.922,-36.181 r90 bottom
R217 "0R" R0201_L#1 3.497,-36.206 r270 bottom
RDH2 "50R" R0201_L#1 72.142,39.753 r0 bottom
RH1 "50R" R0402_L 73.175,65.025 r90 bottom
SH200 "RF_SHIELD_FRAME_BMI-S-202-F" LAIRD_BMI-S-202-F 69.75,-37 r180 bottom locked
TPJ1 "TPJ_SMD" TP_1.0_SMD 60.098,-73.907 r90 bottom locked
TPJ2 "TPJ_SMD" TP_1.0_SMD 60.449,-57.777 r90 bottom locked
TPJ3 "TPJ_SMD" TP_1.0_SMD 60.049,-71.357 r90 bottom locked
TPJ4 "TPJ_SMD" TP_1.0_SMD 61.399,-63.107 r90 bottom locked
TPJ5 "TPJ_SMD" TP_1.0_SMD 57.899,-62.957 r90 bottom locked
TPJ6 "TPJ_SMD" TP_1.0_SMD 61.369,-60.587 r90 bottom locked
TPJ7 "TPJ_SMD" TP_1.0_SMD 58.839,-60.627 r90 bottom locked
TPJ8 "TPJ_SMD" TP_1.0_SMD 57.949,-58.257 r90 bottom locked
TPJ9 "TPJ_SMD" TP_1.0_SMD 70.199,-70.157 r90 bottom locked
TPJ10 "TPJ_SMD" TP_1.0_SMD 67.799,-65.407 r90 bottom locked
TPJ11 "TPJ_SMD" TP_1.0_SMD 68.949,-67.907 r90 bottom locked
TPJ12 "TPJ_SMD" TP_1.0_SMD 68.299,-57.207 r90 bottom locked
TPJ13 "TPJ_SMD" TP_1.0_SMD 66.949,-69.457 r90 bottom locked
TPJ14 "TPJ_SMD" TP_1.0_SMD 68.699,-62.457 r90 bottom locked
TPJ15 "TPJ_SMD" TP_1.0_SMD 68.699,-59.857 r90 bottom locked
TPJ16 "TPJ_SMD" TP_1.0_SMD 66.599,-73.907 r90 bottom locked
TPJ17 "TPJ_SMD" TP_1.0_SMD 57.899,-65.557 r90 bottom locked
TPJ18 "TPJ_SMD" TP_1.0_SMD 50.55,-73.287 r90 bottom locked
TPJ19 "TPJ_SMD" TP_1.0_SMD 48.349,-74.282 r90 bottom locked
U1 "EFR32BG22C224F512IM40" QFN40_M040_5.0X5.0_EP_SL 69.75,-34.95 r90 bottom
U200 "MX25R8035F" BGA8_M040_1.24X1.75_WLCSP 71.65,-41.775 r270 bottom
U201 "SKY13377-313LF" SKY13377-313LF 73.5,21 r270 bottom
U202 "SKY13377-313LF" SKY13377-313LF 73.5,32 r270 bottom
U203 "SKY13377-313LF" SKY13377-313LF 61.88,74.825 r180 bottom
U204 "SKY13377-313LF" SKY13377-313LF 61.84,-2.538 r225 bottom
U205 "CHW-SP16TS-B" QFN32_4X4MM_CHW-SP16TS-B 0,36 r270 bottom
U206 "CHW-SP16TS-B" QFN32_4X4MM_CHW-SP16TS-B 0,-36 r180 bottom
U207 "SN74LVC2G14" SOT-23-6_SN74LVC2G14 75.625,11.925 r0 bottom
U208 "SN74LVC2G14" SOT-23-6_SN74LVC2G14 75.625,6.925 r0 bottom
X1 "38.4 MHz" KDS_DSX211SH_2016 67.9,-39.725 r90 bottom
X2 "32.768 kHz" X_MCS_CM8V-T1A 73.9,-38.706 r0 bottom

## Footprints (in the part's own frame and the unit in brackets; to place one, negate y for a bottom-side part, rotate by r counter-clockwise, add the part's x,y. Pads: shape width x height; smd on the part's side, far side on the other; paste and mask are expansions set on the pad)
3MM_PLATED [mm] "3MM_PLATED"
  round 6.2 / inner round 3.6 / far side round 6.2 hole 3.2: 1(0,0)
6LAYER_RECT_DP_PATCH_24mm2_14mmRIS_31mm6CELL_6mm1FP [mm]
  round 1.3 / inner round 0 / far side round 1.3 hole 0.8 paste+0 mask+0: 1(6,0) 2(0,6)
  Top Layer region: -12.1,-12.1 12.1,-12.1 12.1,12.1 -12.1,12.1
  Top Layer pour cut-out: -15.8,-15.8 15.8,-15.8 15.8,15.8 -15.8,15.8
  IM3 Signal pour cut-out: -15.8,-15.8 15.8,-15.8 15.8,15.8 -15.8,15.8
  IM1 RIS pour cut-out: 15.8,15.8 -15.8,15.8 -15.8,14.3 15.8,14.3
  IM1 RIS pour cut-out: 15.8,-15.8 15.8,15.8 14.3,15.8 14.3,-15.8
  IM1 RIS pour cut-out: -15.8,-15.8 15.8,-15.8 15.8,-14.3 -15.8,-14.3
  IM1 RIS pour cut-out: 6.3,8.3 6.3,6.3 8.3,6.3 8.3,8.3
  IM1 RIS pour cut-out: 6.3,-6.3 6.3,-8.3 8.3,-8.3 8.3,-6.3
  IM1 RIS pour cut-out: -8.3,-6.3 -8.3,-8.3 -6.3,-8.3 -6.3,-6.3
  IM1 RIS pour cut-out: -8.3,8.3 -8.3,6.3 -6.3,6.3 -6.3,8.3
  IM1 RIS pour cut-out: -15.8,-15.8 -15.8,15.8 -14.3,15.8 -14.3,-15.8
  IM1 RIS pour cut-out: -15.8,0.3 15.8,0.3 15.8,-0.3 -15.8,-0.3
  IM1 RIS pour cut-out: -0.3,-15.8 -0.3,15.8 0.3,15.8 0.3,-15.8
  IM2 Signal pour cut-out: -15.8,-15.8 15.8,-15.8 15.8,15.8 -15.8,15.8
  Multi-Layer pour cut-out: 6,-1 5.617,-0.924 5.293,-0.707 5.076,-0.383 5,0 5,0 5.076,0.383 5.293,0.707 5.617,0.924 6,1 6,1 6.383,0.924 6.707,0.707 6.924,0.383 7,0 7,0 6.924,-0.383 6.707,-0.707 6.383,-0.924 6,-1
  Multi-Layer pour cut-out: 0,5 -0.383,5.076 -0.707,5.293 -0.924,5.617 -1,6 -1,6 -0.924,6.383 -0.707,6.707 -0.383,6.924 0,7 0,7 0.383,6.924 0.707,6.707 0.924,6.383 1,6 1,6 0.924,5.617 0.707,5.293 0.383,5.076 0,5
90DEG_HYBRID_EUROCIRCUITS_6LAYER_0mm2 [mm]
  rect 1x0.33 smd paste-1: 1(-9.6,2.765) 2(-9.6,-2.765) 3(9.6,-2.765) 4(9.6,2.765)
  Top Layer pour cut-out: -10,4.8 -10,-4.8 10,-4.8 10,4.8
  Top Layer region: -9.15,-2.93 -8.48,-2.93 -8.15,-3.2 8.15,-3.2 8.48,-2.93 9.15,-2.93 9.15,-2.6 8.48,-2.6 8.48,-1.7 8.05,-1.27 1.95,-1.27 1.95,1.27 8.05,1.27 8.48,1.7 8.48,2.6 8.15,2.6 8.15,1.6 2.05,1.6 1.62,1.17 1.62,-1.17 2.05,-1.6 8.15,-1.6 8.15,-2.6 -8.15,-2.6 -8.15,-1.6 -2.05,-1.6 -1.62,-1.17 -1.62,1.17 -2.05,1.6 -8.15,1.6 -8.15,2.6 9.15,2.6 9.15,2.93 8.48,2.93 8.15,3.2 -8.15,3.2 -8.48,2.93 -9.15,2.93 -9.15,2.6 -8.48,2.6 -8.48,1.7 -8.05,1.27 -1.95,1.27 -1.95,-1.27 -8.05,-1.27 -8.48,-1.7 -8.48,-2.6 -9.15,-2.6
BGA8_M040_1.24X1.75_WLCSP [mm] "BGA, 8 pin. U100"
  round 0.21 smd mask+0.038: A1(-0.35,0.4) A3(0.35,0.4) B2(0,0.2) C1(-0.35,0) C3(0.35,0) D2(0,-0.2) E1(-0.35,-0.4) E3(0.35,-0.4)
  body extent -0.63,-0.89 0.63,0.88, height 0.52
C0201_L [mm] "Capacitor, Chip; 0.60 mm L X 0.30 mm W X 0.33 mm H body"
  rrect52% 0.31x0.34 smd: 1(-0.275,0) 2(0.275,0)
  body extent -0.3,-0.15 0.3,0.15, height 0.3
C0201_NOPASTE [mm] "Capacitor, Chip; 0.60 mm L X 0.30 mm W X 0.33 mm H body"
  rrect52% 0.31x0.34 smd paste-0.34: 1(-0.275,0) 2(0.275,0)
  body extent -0.3,-0.15 0.3,0.15, height 0.3
C0402_L [mm] "Chip Capacitor, 2-Leads, Body 1.0x0.5mm, IPC High Density"
  rrect20% 0.6x0.5 smd mask+0.051: 1(-0.45,0) 2(0.45,0)
  body extent -0.5,-0.25 0.5,0.25, height 0.6
C0603_L [mm] "Capacitor, 0603, High Density (C)"
  rrect25% 0.8x0.85 smd: 1(-0.7,0) 2(0.7,0)
  body extent -0.8,-0.4 0.8,0.4, height 0.95
C0805_L [mm] "Capacitor, 0805"
  rrect25% 0.95x1.35 smd: 1(-0.8,0) 2(0.8,0)
  body extent -1.1,-0.72 1.1,0.72, height 1.45
COAX_HIROSE_U.FL_CL331-0471 [mm] "COAX_HIROSE_U.FL_CL331-0471"
  rrect20% 1.05x1.1 smd mask+0.051: 1(0,1.6)
  rrect20% 1.05x2.25 smd mask+0.051: 2(-1.5,0) 3(1.5,0)
  Top Layer pour cut-out: -0.85,0.9 0.85,0.9 0.85,0.9 0.85,-1.2 -0.85,-1.2 -0.85,-1.2
  body extent -1.3,-1.55 1.3,1.3, height 0.9
COIL_0201_L [mm] "JELF243C-0021"
  rrect10% 0.3x0.3 smd: 1(-0.3,0) 2(0.3,0)
  body extent -0.32,-0.17 0.32,0.17, height 0.33
COIL_1008_L [mil] "Chip Inductors, 1008 (2520), Coilcraft (190207)"
  rrect25% 40x100 smd: 1(-45,0) 2(45,0)
  body extent -58,-55 58,55, height 80
COIL_MUR_BLM18_0603 [mm] "COIL_MUR_BLM18P_0603"
  rrect25% 0.85x0.7 smd mask+0.051: 1(-0.7,0) 2(0.7,0)
  body extent -0.88,-0.48 0.87,0.48, height 0.95
FTSH_106_01_L_DV_K [mil] "FTSH-105-01-L-DV-K-P-TR"
  rrect50% 29x110 smd: 1(-125,-80) 2(-125,80) 3(-75,-80) 4(-75,80) 5(-25,-80) 6(-25,80) 7(25,-80) 8(25,80) 9(75,-80) 10(75,80) 11(125,-80) 12(125,80)
  body extent -150,-115 150,115, height 231
HEADER_1X13_2.54MM_TH [mm] "Connector; Header; 2 Position"
  rrect10% 1.5x1.5 hole 0.9: 1(-15.242,0)
  round 1.5 hole 0.9: 2(-12.702,0) 3(-10.162,0) 4(-7.622,0) 5(-5.082,0) 6(-2.542,0) 7(-0.002,0) 8(2.542,0) 9(5.082,0) 10(7.622,0) 11(10.162,0) 12(12.702,0) 13(15.242,0)
  body extent -16.51,-1.27 16.51,1.27, height 9.7
KDS_DSX211SH_2016 [mm] "Copy of Silabs CE  X_KDS_DSX211SH_2.0X1.65-4"
  rrect20% 0.9x0.8 smd mask+0.051: 1(-0.7,-0.55) 2(0.7,-0.55) 3(0.7,0.55) 4(-0.7,0.55)
  body extent -1.07,-0.87 1.08,0.88, height 0.5
LAIRD_BMI-S-202-F [mm] "laired BMI-S-202-F"
  rrect20% 0.75x4.5 smd paste+0 mask+0.05: 1(-8.25,-6.375) 1(-8.25,6.375) 1(8.25,-6.375) 1(8.25,6.375)
  rrect20% 0.75x3.8 smd paste+0 mask+0.05: 1(-8.25,0) 1(8.25,0)
  rrect20% 4.5x0.75 smd paste+0 mask+0.05: 1(-6.375,8.25) 1(-6.375,-8.25) 1(6.375,8.25) 1(6.375,-8.25)
  rrect20% 3.8x0.75 smd paste+0 mask+0.05: 1(0,-8.25) 1(0,8.25)
  body extent -8.6,-8.6 8.6,8.6, height 5.5
LED0402_L [mm] "Led smd 0402"
  rrect25% 0.5x0.5 smd: 1(-0.525,0) 2(0.525,0)
  body extent -0.5,-0.25 0.5,0.25, height 0.3
LOGO_SILABS_W12.0 [mm] "LOGO_SILABS_W12.0 (170217)"
  silkscreen extent 0.03,0.03 11.99,5.88
PCB_ASSEMBLY_FRAME_A3 [mm]
PCB_SPEC_6_LAYER_BLINDVIA [mm] "Patchantenna_version"
QFN32_4X4MM_CHW-SP16TS-B [mm]
  rect 1x1 smd: 0(0,0)
  rect 0.59x0.2 smd: 1(-1.985,1.4) 8(-1.985,-1.4) 17(1.985,-1.4) 24(1.985,1.4)
  rect 0.76x0.2 smd: 2(-1.985,1) 3(-1.985,0.6) 4(-1.985,0.2) 5(-1.985,-0.2) 6(-1.985,-0.6) 7(-1.985,-1) 18(1.985,-1) 19(1.985,-0.6) 20(1.985,-0.2) 21(1.985,0.2) 22(1.985,0.6) 23(1.985,1)
  rect 0.2x0.59 smd: 9(-1.4,-1.985) 16(1.4,-1.985) 25(1.4,1.985) 32(-1.4,1.985)
  rect 0.2x0.76 smd: 10(-1,-1.985) 11(-0.6,-1.985) 12(-0.2,-1.985) 13(0.2,-1.985) 14(0.6,-1.985) 15(1,-1.985) 26(1,1.985) 27(0.6,1.985) 28(0.2,1.985) 29(-0.2,1.985) 30(-0.6,1.985) 31(-1,1.985)
  Top Layer region: -1.897,1.301 -1.649,1.301 -1.649,1.333 -1.817,1.5 -1.897,1.5 -1.897,1.301
  Top Layer region: -1.918,-1.3 -1.648,-1.3 -1.648,-1.332 -1.816,-1.5 -1.918,-1.5 -1.918,-1.3
  Top Layer region: -1.301,-1.946 -1.301,-1.648 -1.333,-1.648 -1.501,-1.816 -1.501,-1.946 -1.301,-1.946
  Top Layer region: 1.3,-1.938 1.3,-1.646 1.332,-1.646 1.5,-1.814 1.5,-1.938 1.3,-1.938
  Top Layer region: 2.001,-1.299 1.65,-1.299 1.65,-1.331 1.818,-1.499 2.001,-1.499 2.001,-1.299
  Top Layer region: 1.976,1.301 1.649,1.301 1.649,1.333 1.817,1.501 1.976,1.501 1.976,1.301
  Top Layer region: 1.3,1.955 1.3,1.647 1.332,1.647 1.5,1.815 1.5,1.955 1.3,1.955
  Top Layer region: -1.3,1.96 -1.3,1.647 -1.332,1.647 -1.5,1.815 -1.5,1.96 -1.3,1.96
  Top Layer region: -1.4,1.05 -1.05,1.404 1.4,1.404 1.4,-1.4 -1.4,-1.4 -1.4,1.05
  silkscreen extent -2,1.8 -1.8,2, body extent -2,-2 2,2, height 0.55
QFN40_M040_5.0X5.0_EP_SL [mm] "QFN48_M050_SQ7.0_EP, SiLabs, High Density (C)"
  rrect5% 3.85x3.85 smd paste-1.95 mask+0.05: 0(0,0)
  rrect10% 0.74x0.22 smd mask+0.05: 1(-2.495,1.8) 2(-2.495,1.4) 3(-2.495,1) 4(-2.495,0.6) 5(-2.495,0.2) 6(-2.495,-0.2) 7(-2.495,-0.6) 8(-2.495,-1) 9(-2.495,-1.4) 10(-2.495,-1.8) 21(2.495,-1.8) 22(2.495,-1.4) 23(2.495,-1) 24(2.495,-0.6) 25(2.495,-0.2) 26(2.495,0.2) 27(2.495,0.6) 28(2.495,1) 29(2.495,1.4) 30(2.495,1.8)
  rrect10% 0.22x0.74 smd mask+0.05: 11(-1.8,-2.495) 12(-1.4,-2.495) 13(-1,-2.495) 14(-0.6,-2.495) 15(-0.2,-2.495) 16(0.2,-2.495) 17(0.6,-2.495) 18(1,-2.495) 19(1.4,-2.495) 20(1.8,-2.495) 31(1.8,2.495) 32(1.4,2.495) 33(1,2.495) 34(0.6,2.495) 35(0.2,2.495) 36(-0.2,2.495) 37(-0.6,2.495) 38(-1,2.495) 39(-1.4,2.495) 40(-1.8,2.495)
  body extent -2.5,-2.5 2.5,2.5, height 1.01
R0201_L#1 [mm] "Resistor, Chip; 0.60 mm L X 0.30 mm W X 0.28 mm H body"
  rrect52% 0.31x0.34 smd: 1(-0.275,0) 2(0.275,0)
  body extent -0.3,-0.15 0.3,0.15, height 0.23
R0201_L#2 [mm] "Resistor (Chip2PinSM127P600-8N) (170921)"
  rrect25% 0.34x0.32 smd: 1(-0.3,0) 2(0.3,0)
  body extent -0.32,-0.13 0.32,0.13, height 0.3
R0402_L [mm] "Chip Resistor, 2-Leads, Body 1.0x0.5mm, IPC High Density"
  rrect20% 0.6x0.6 smd mask+0.051: 1(-0.45,0) 2(0.45,0)
  body extent -0.5,-0.25 0.5,0.25, height 0.6
SKY13377-313LF [mm]
  rect 0.442x0.35 smd paste-0.05 mask+0.05: 1(-0.929,0.95) 2(-0.929,0) 3(-0.929,-0.95) 4(0.929,-0.95) 5(0.929,0) 6(0.929,0.95)
  round 0.1 smd paste-0.1 mask-0.1: 7(0,0)
  Top Layer region: -0.41,-0.61 -0.487,-0.595 -0.551,-0.551 -0.595,-0.487 -0.61,-0.41 -0.61,-0.41 -0.61,-0.175 -0.744,-0.175 -0.744,0.175 -0.61,0.175 -0.61,0.41 -0.51,0.437 -0.437,0.51 -0.41,0.61 -0.41,0.61 -0.102,0.61 -0.102,1.65 0.101,1.65 0.101,0.603 0.168,0.558 0.214,0.49 0.23,0.41 0.23,0.41 0.23,-0.41 0.215,-0.492 0.17,-0.562 0.101,-0.61 0.101,-0.61 0.101,-1.65 -0.102,-1.65 -0.102,-0.61
  body extent -1,-1.51 1.01,1.5, height 0.4
SOT-23-6_SN74LVC2G14 [mm]
  rect 1x0.7 smd paste-0.025: 1(-1.27,0.953) 2(-1.27,0) 3(-1.27,-0.953) 4(1.27,-0.953) 5(1.27,0) 6(1.27,0.953)
  body extent -1.21,-1.4 1.21,1.4, height 1.09
TP_1.0_SMD [mm] "Test Point, 1.0 mm, SMD"
  round 1 smd paste-0.501: 1(0,0)
  body extent -0.2,-0.2 0.2,0.2, height 0.01
X2DFN2_1.0x0.6_0.65P [mm] "ESD Diode"
  rrect20% 0.47x0.6 smd mask+0.051: 1(-0.365,0) 2(0.365,0)
  body extent -0.5,-0.25 0.5,0.25, height 0.6
X_MCS_CM8V-T1A [mm] "Crystal MCS CM8V-T1A (2 pin)"
  rrect25% 0.8x1.5 smd mask+0.051: 1(-0.75,0)
  rrect25% 0.85x1.5 smd mask+0.051: 2(0.75,0)
  body extent -1,-0.6 1,0.6, height 0.95

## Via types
v1: diameter 0.6, hole 0.25, IM4 GND to Bottom Layer, tented bottom, 3924 vias
v2: diameter 0.6, hole 0.25, Top Layer to Bottom Layer, tented both sides, 851 vias
v3: diameter 0.6, hole 0.25, IM4 GND to Bottom Layer, tented both sides, 179 vias

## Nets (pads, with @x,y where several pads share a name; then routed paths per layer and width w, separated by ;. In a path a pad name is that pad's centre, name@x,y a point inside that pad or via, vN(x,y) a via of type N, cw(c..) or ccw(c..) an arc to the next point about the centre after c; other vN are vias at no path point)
3V3: TPJ10.1
5V: TPJ12.1
50R_ANT_H1: ANT1.1 CH1.1 U205.25 | length 120
  Bottom Layer w0.2: -3.641,33.355 -2.41,34.6 U205.25@-1.985,34.6
  Bottom Layer w0.28: ANT1.1@-54,48 CH1.1@-54,49.5 -54,61.525 -58.075,65.6 -64.05,65.6 -68.15,61.5 -68.15,46.475 -57.925,36.25 -35.6,36.25 -32.575,33.225 -16.15,33.225 -13.852,30.927 -6.983,30.927 -3.641,33.355
50R_ANT_H2: ANT2.1 CH2.1 U205.27 | length 120
  Bottom Layer w0.2: -4.537,35.036 -2.821,35.4 U205.27@-1.985,35.4
  Bottom Layer w0.28: ANT2.1@-18,48 CH2.1@-18,46.5 -18,44.55 -21.675,40.875 -28.275,40.875 -35.925,48.525 -35.925,73.225 -34.125,75.025 -31.3,75.025 -29.375,73.1 -29.375,53.05 -27.3,50.975 -15.075,50.975 -11.6,47.5 -11.6,37.476 -8.521,34.397 -7.6,34.397 -7.004,34.521 -4.537,35.036
50R_ANT_H3: ANT3.1 CH3.1 U205.13 | length 120
  Bottom Layer w0.2: U205.13@1.985,35.8 2.767,35.8 4.57,36.008
  Bottom Layer w0.28: 4.57,36.008 6.1,37.538 6.1,59.35 11.55,64.8 37.975,64.8 39.1,63.675 39.1,61.3 37.975,60.175 22.475,60.175 20.625,58.325 20.625,54.9 19.525,53.8 17.525,53.8 16.375,54.95 16.375,58.3 14.9,59.775 12.175,59.775 10.625,58.225 10.625,49.6 12.225,48 ANT3.1@18,48
50R_ANT_H4: ANT4.1 CH4.1 U205.15 | length 120
  Bottom Layer w0.2: U205.15@1.985,35 2.588,35 4.111,34.17
  Bottom Layer w0.28: 4.111,34.17 8.61,32.166 16.691,32.166 20.7,36.175 42.925,36.175 45.8,39.05 57.325,39.05 58.425,40.15 58.425,41.9 57.275,43.05 51.55,43.05 47.738,46.862 47.738,53.087 42.85,57.975 42.85,63.05 45,65.2 50.025,65.2 52.125,63.1 52.125,49.875 CH4.1@52.939,49.061 ANT4.1@54,48
50R_ANT_H5: ANT5.1 CH5.1 U205.23 | length 120
  Bottom Layer w0.2: -2.25,32.103 -1.079,33.362 -1,33.447 U205.23@-1,34.015
  Bottom Layer w0.28: ANT5.1@-54,12 CH5.1@-55.061,13.061 -58.3,16.3 -71.875,16.3 -74.675,13.5 -74.675,7.4 -71.7,4.425 -55,4.425 -42.375,17.05 -42.375,20.668 -36.218,26.825 -5.88,26.825 -4.501,28.205 -2.25,32.103
50R_ANT_H6: ANT6.1 CH6.1 U206.20 | length 120
  Bottom Layer w0.2: -4.475,-36.47 -2.784,-36.2 U206.20@-1.985,-36.2
  Bottom Layer w0.28: ANT6.1@-18,12 -21.3,12 -22.825,10.475 -22.825,8.65 -21.275,7.1 -18.925,7.1 -17.825,6 -17.825,4.3 -18.9,3.225 -26.7,3.225 -28.175,1.75 -28.175,-13.675 -30.975,-16.475 -34.35,-16.475 -36.025,-18.15 -36.025,-20.1 -34.775,-21.35 -33.125,-21.35 -31.7,-22.775 -31.7,-26.175 -36.55,-31.025 -41.375,-31.025 -42.8,-32.45 -42.8,-34.55 -41.525,-35.825 -12.45,-35.825 -11.439,-36.836 -7.956,-36.836 -4.475,-36.47
50R_ANT_H7: ANT7.1 CH7.1 U206.23 | length 120
  Bottom Layer w0.2: -3.897,-33.75 -2.552,-35 U206.23@-1.985,-35
  Bottom Layer w0.28: -3.897,-33.75 -6.928,-32 -8.875,-30.053 -8.875,-4.8 -2.875,1.2 -2.875,2.775 3.25,8.9 3.25,17.5 8.925,23.175 24.25,23.175 31.35,16.075 31.35,10.125 27.55,6.325 20,6.325 18,8.325 CH7.1@18,10.5 ANT7.1@18,12
50R_ANT_H8: ANT8.1 CH8.1 U205.17 | length 120
  Bottom Layer w0.2: U205.17@1.4,34.015 1.4,33.594 3.011,32.656
  Bottom Layer w0.28: 3.011,32.656 5.353,30.055 7.367,28.041 47.759,28.041 48.65,27.15 48.65,25.025 47.55,23.925 37.175,23.925 36.075,22.825 36.075,21.125 39.475,17.725 39.475,14.425 40.625,13.275 41.9,13.275 42.9,14.275 42.9,18.35 43.8,19.25 45.25,19.25 46.175,18.325 46.175,10.825 47.2,9.8 48.75,9.8 49.775,10.825 49.775,18.8 50.925,19.95 52.8,19.95 54,18.75 CH8.1@54,13.5 ANT8.1@54,12
50R_ANT_H9: ANT9.1 CH9.1 U205.21 | length 120
  Bottom Layer w0.2: -0.47,31.525 -0.2,33.215 U205.21@-0.2,34.015
  Bottom Layer w0.28: ANT9.1@-54,-24 -57,-27 -60.05,-27 -61.7,-25.35 -61.7,-22.225 -59.4,-19.925 -52.675,-19.925 -49.55,-23.05 -45.925,-23.05 -43.875,-21 -43.875,6.025 -27.35,22.55 -4.4,22.55 -0.836,26.114 -0.836,28.044 -0.47,31.525
50R_ANT_H10: ANT10.1 CH10.1 U206.21 | length 120
  Bottom Layer w0.2: -4.475,-35.53 -2.784,-35.8 U206.21@-1.985,-35.8
  Bottom Layer w0.28: ANT10.1@-18,-24 CH10.1@-19.5,-24 -20.325,-24 -21.35,-22.975 -21.35,-21.675 -20.375,-20.7 -17.35,-20.7 -14.4,-23.65 -14.4,-27.15 -16.225,-28.975 -22.225,-28.975 -24.65,-26.55 -24.65,-20.8 -21.275,-17.425 -21.275,-1 -22.325,0.05 -24.025,0.05 -25.025,-0.95 -25.025,-15.75 -28.4,-19.125 -28.4,-30.425 -26.5,-32.325 -12.575,-32.325 -9.736,-35.164 -7.956,-35.164 -4.475,-35.53
50R_ANT_H11: ANT11.1 CH11.1 U206.27 | length 120
  Bottom Layer w0.2: -0.936,-31.598 -0.622,-33.103 -0.6,-33.21 U206.27@-0.6,-34.015
  Bottom Layer w0.28: -0.936,-31.598 -1.362,-29.593 -1.362,-27.409 0.1,-25.948 0.1,-13.6 5.3,-8.4 7.425,-8.4 8.925,-9.9 8.925,-12.2 4.375,-16.75 4.375,-23.425 6.375,-25.425 10.625,-25.425 12.5,-23.55 12.5,-3.825 13.575,-2.75 15.775,-2.75 16.875,-3.85 16.875,-18.975 18.975,-21.075 26.2,-21.075 27.025,-21.9 27.025,-23.225 26.25,-24 CH11.1@19.5,-24 ANT11.1@18,-24
50R_ANT_H12: ANT12.1 CH12.1 U206.26 | length 120
  Bottom Layer w0.2: -1.83,-31.889 -1,-33.379 U206.26@-1,-34.015
  Bottom Layer w0.28: -1.83,-31.889 -3.675,-27.747 -3.675,-12.525 8.95,0.1 32.825,0.1 39.75,-6.825 39.75,-27.4 41.925,-29.575 44.95,-29.575 47.075,-27.45 47.075,-21.725 49.2,-19.6 51.9,-19.6 54,-21.7 CH12.1@54,-22.5 ANT12.1@54,-24
50R_ANT_H13: ANT13.1 CH13.1 U206.19 | length 120
  Bottom Layer w0.2: -4.28,-37.391 -2.647,-36.6 U206.19@-1.985,-36.6
  Bottom Layer w0.28: ANT13.1@-54,-60 -57.675,-63.675 -61.775,-63.675 -65.725,-59.725 -65.725,-46.575 -62.475,-43.325 -57.025,-43.325 -53.325,-47.025 -53.325,-54.45 -49.375,-58.4 -43.725,-58.4 -40.2,-54.875 -40.2,-41.075 -39.181,-40.056 -12.482,-40.056 -4.28,-37.391
50R_ANT_H14: ANT14.1 CH14.1 U206.17 | length 120
  Bottom Layer w0.2: -3.344,-39.011 -2.405,-37.4 U206.17@-1.985,-37.4
  Bottom Layer w0.28: ANT14.1@-18,-60 CH14.1@-16.5,-60 -14.8,-60 -12.625,-62.175 -12.625,-65.8 -14.8,-67.975 -41.6,-67.975 -43.6,-69.975 -43.6,-72.75 -41.625,-74.725 -11.125,-74.725 -7.8,-71.4 -7.8,-43.137 -6.662,-41.999 -3.344,-39.011
50R_ANT_H15: ANT15.1 CH15.1 U206.15 | length 120
  Bottom Layer w0.2: -1.83,-40.111 -1,-38.589 U206.15@-1,-37.985
  Bottom Layer w0.28: -1.83,-40.111 -3.161,-43.101 -3.161,-45.064 0.55,-48.775 18.2,-48.775 19.3,-49.875 19.3,-51.925 18.2,-53.025 5.35,-53.025 4.3,-54.075 4.3,-55.9 5.375,-56.975 21.3,-56.975 25.3,-60.975 25.3,-65.75 23.1,-67.95 6.75,-67.95 4.575,-65.775 4.575,-62.4 6.975,-60 ANT15.1@18,-60
50R_ANT_H16: ANT16.1 CH16.1 U206.14 | length 120
  Bottom Layer w0.2: -0.936,-40.402 -0.6,-38.694 U206.14@-0.6,-37.985
  Bottom Layer w0.28: -0.936,-40.402 -1.663,-43.825 -1.663,-44.487 -0.475,-45.675 23.225,-45.675 30.45,-52.9 48.02,-52.9 49.212,-54.091 49.212,-55.653 47.865,-57 42,-57 40.75,-58.25 40.75,-59.975 42.075,-61.3 48.25,-61.3 49.375,-62.425 49.375,-64.075 48.275,-65.175 41.025,-65.175 39.975,-66.225 39.975,-67.95 41.15,-69.125 51.9,-69.125 54,-67.025 CH16.1@54,-61.5 ANT16.1@54,-60
50R_ANT_V1: ANT1.2 CV1.1 U205.26 | length 120
  Bottom Layer w0.2: -4.111,34.17 -2.622,35 U205.26@-1.985,35
  Bottom Layer w0.28: ANT1.2@-48,54 CV1.1@-48,55.5 -48,70.175 -50.275,72.45 -56.8,72.45 -57.95,73.6 -57.95,75.675 -56.7,76.925 -44.825,76.925 -41.125,73.225 -41.125,47.475 -29.725,36.075 -14.829,36.075 -11.5,32.746 -7.308,32.746 -4.111,34.17
50R_ANT_V2: ANT2.2 CV2.1 U205.28 | length 120
  Bottom Layer w0.2: -4.535,36.004 -2.916,35.8 U205.28@-1.985,35.8
  Bottom Layer w0.28: ANT2.2@-12,54 -23.275,54 -25.15,55.875 -25.15,59.175 -23.15,61.175 -12.225,61.175 -10.45,62.95 -10.45,66.2 -12.375,68.125 -22,68.125 -24.325,70.45 -24.325,74.45 -22.275,76.5 -8.475,76.5 -5.675,73.7 -5.675,42.175 -7.6,40.25 -7.6,37.867 -5.911,36.178 -4.535,36.004
50R_ANT_V3: ANT3.2 CV3.1 U205.14 | length 120
  Bottom Layer w0.2: U205.14@1.985,35.4 2.693,35.4 4.402,35.064
  Bottom Layer w0.28: 4.402,35.064 9.807,33.916 11.541,33.916 13.425,35.8 13.425,37.725 12.25,38.9 10.35,38.9 9.225,40.025 9.225,41.7 10.3,42.775 19.975,42.775 22.05,44.85 22.05,47.925 23.2,49.075 24.975,49.075 26.075,47.975 26.075,41.8 28.15,39.725 30.3,39.725 32.35,41.775 43.025,41.775 44.35,43.1 44.35,44.975 42.965,46.36 30.95,46.36 29.625,47.685 29.625,49.475 30.75,50.6 38.075,50.6 39.525,52.05 39.525,54.5 37.9,56.125 26.125,56.125 ANT3.2@24,54
50R_ANT_V4: ANT4.2 CV4.1 U205.16 | length 120
  Bottom Layer w0.2: U205.16@1.985,34.6 2.405,34.6 3.641,33.355
  Bottom Layer w0.28: 3.641,33.355 7.858,30.291 20.65,30.291 22.434,32.075 44.375,32.075 48.3,36 50.675,36 51.925,34.75 51.925,32.175 53.35,30.75 60.025,30.75 61.95,32.675 61.95,46.525 56.325,52.15 56.325,63.2 58.1,64.975 61.375,64.975 63.175,63.175 63.175,57.175 ANT4.2@60,54
50R_ANT_V5: ANT5.2 CV5.1 U205.24 | length 120
  Bottom Layer w0.2: -3.011,32.656 -1.4,33.598 U205.24@-1.4,34.015
  Bottom Layer w0.28: ANT5.2@-48,18 CV5.1@-48,19.5 -48,22.55 -50.125,24.675 -72.3,24.675 -75.35,27.725 -75.35,33.2 -72.432,36.118 -66.893,36.118 -60.725,29.95 -16.825,29.95 -15.75,28.875 -6.508,28.875 -5.578,29.805 -3.011,32.656
50R_ANT_V6: ANT6.2 CV6.1 U205.20 | length 120
  Bottom Layer w0.2: U205.20@0.2,34.015 0.2,33.215 0.47,31.525
  Bottom Layer w0.28: ANT6.2@-12,18 -23.525,18 -35.75,5.775 -35.75,-7.9 -36.85,-9 -38.75,-9 -39.85,-7.9 -39.85,5.975 -25.475,20.35 -2.1,20.35 0.836,23.286 0.836,28.044 0.47,31.525
50R_ANT_V7: ANT7.2 CV7.1 U206.24 | length 120
  Bottom Layer w0.2: -3.344,-32.989 -2.401,-34.6 U206.24@-1.985,-34.6
  Bottom Layer w0.28: -3.344,-32.989 -5.945,-30.647 -7.125,-29.467 -7.125,-7.775 0.35,-0.3 0.35,1.425 5.35,6.425 14.1,6.425 15.5,7.825 15.5,10.175 13.85,11.825 8.675,11.825 6.925,13.575 6.925,16.7 10.825,20.6 20.35,20.6 21.1,19.85 21.1,18.5 20.375,17.775 13.3,17.775 12.45,16.925 12.45,15.675 13.4,14.725 19,14.725 21,12.725 22.725,12.725 24,14 CV7.1@24,16.5 ANT7.2@24,18
50R_ANT_V8: ANT8.2 CV8.1 U205.18 | length 120
  Bottom Layer w0.2: U205.18@1,34.015 1,33.451 2.25,32.103
  Bottom Layer w0.28: 2.25,32.103 3.876,29.287 4,29.072 7.419,25.653 26.447,25.653 35.6,16.5 35.6,11.95 47.225,0.325 51.6,0.325 56.8,5.525 59.95,5.525 62.475,8.05 62.475,11.475 57,16.95 57,20.375 53.4,23.975 53.4,26.05 54.85,27.5 58.95,27.5 60,26.45 CV8.1@60,19.5 ANT8.2@60,18
50R_ANT_V9: ANT9.2 CV9.1 U205.22 | length 120
  Bottom Layer w0.2: -1.391,31.72 -0.6,33.329 U205.22@-0.6,34.015
  Bottom Layer w0.28: ANT9.2@-48,-18 -51.75,-14.25 -67.1,-14.25 -68.8,-12.55 -68.8,-8.325 -67.1,-6.625 -52.625,-6.625 -49.975,-3.975 -49.975,4.375 -29.7,24.65 -5.543,24.65 -2.795,27.399 -1.391,31.72
50R_ANT_V10: ANT10.2 CV10.1 U206.22 | length 120
  Bottom Layer w0.2: -4.28,-34.609 -2.914,-35.281 -2.67,-35.4 U206.22@-1.985,-35.4
  Bottom Layer w0.28: ANT10.2@-12,-18 CV10.1@-13.061,-16.939 -15.25,-14.75 -15.25,-3.625 -11.6,0.025 -7.85,0.025 -6.775,1.1 -6.775,2.475 -7.8,3.5 -10.1,3.5 -11.55,4.95 -11.55,7.05 -10.1,8.5 -1.4,8.5 -0.375,9.525 -0.375,10.9 -1.35,11.875 -12.475,11.875 -14.825,9.525 -14.825,0.975 -18.625,-2.825 -18.625,-15.775 -11.575,-22.825 -11.575,-29.561 -7.608,-33.528 -4.28,-34.609
50R_ANT_V11: ANT11.2 CV11.1 U206.28 | length 120
  Bottom Layer w0.2: U206.28@-0.2,-34.015 -0.2,-33.085 0,-31.5
  Bottom Layer w0.28: 0,-31.5 0,-30.525 1.875,-28.65 32.725,-28.65 35.8,-25.575 35.8,-8.175 31.2,-3.575 22.55,-3.575 21.1,-5.025 21.1,-7.15 22.725,-8.775 30.525,-8.775 32.25,-10.5 32.25,-18.275 31.15,-19.375 29.475,-19.375 28.3,-18.2 28.3,-13.525 26.925,-12.15 24.05,-12.15 22.375,-13.825 22.375,-16.375 ANT11.2@24,-18
50R_ANT_V12: ANT12.2 CV12.1 U206.25 | length 120
  Bottom Layer w0.2: -2.645,-32.359 -1.4,-33.59 U206.25@-1.4,-34.015
  Bottom Layer w0.28: -2.645,-32.359 -5.4,-28.568 -5.4,-9.875 7.625,3.15 38.875,3.15 49.95,-7.925 49.95,-9.95 48.4,-11.5 44.975,-11.5 43.625,-12.85 43.625,-14.65 45.075,-16.1 53.75,-16.1 55.65,-18 ANT12.2@60,-18
50R_ANT_V13: ANT13.2 CV13.1 U205.19 | length 120
  Bottom Layer w0.2: U205.19@0.6,34.015 0.6,33.352 1.391,31.72
  Bottom Layer w0.28: ANT13.2@-48,-54 CV13.1@-48,-52.5 -48,-31.8 -39.425,-23.225 -39.425,-17.1 -31.925,-9.6 -31.925,4.95 -22.275,14.6 -4.225,14.6 2.75,21.575 2.75,27.536 1.391,31.72
50R_ANT_V14: ANT14.2 CV14.1 U206.18 | length 120
  Bottom Layer w0.2: -3.897,-38.25 -2.548,-37 U206.18@-1.985,-37
  Bottom Layer w0.28: ANT14.2@-12,-54 CV14.1@-13.061,-55.061 -14.275,-56.275 -20.15,-56.275 -24.925,-61.05 -34.275,-61.05 -36.1,-59.225 -36.1,-53.875 -34.125,-51.9 -15.175,-51.9 -14.15,-50.875 -14.15,-48.925 -15.2,-47.875 -35,-47.875 -36.15,-46.725 -36.15,-44.975 -35.1,-43.925 -11.414,-43.925 -8.258,-40.768 -3.897,-38.25
50R_ANT_V15: ANT15.2 CV15.1 U206.16 | length 120
  Bottom Layer w0.2: -2.645,-39.641 -1.4,-38.405 U206.16@-1.4,-37.985
  Bottom Layer w0.28: -2.645,-39.641 -4.937,-42.796 -4.937,-47.5 0.1,-52.537 0.1,-65.3 -3.85,-69.25 -3.85,-73.65 -1.2,-76.3 2.65,-76.3 5.425,-73.525 10.15,-73.525 12.9,-76.275 30.825,-76.275 35.975,-71.125 35.975,-68.425 34.125,-66.575 32.05,-66.575 30.775,-65.3 30.775,-63.275 32,-62.05 34.425,-62.05 36.1,-60.375 36.1,-57.775 34.65,-56.325 26.325,-56.325 ANT15.2@24,-54
50R_ANT_V16: ANT16.2 CV16.1 U206.13 | length 120
  Bottom Layer w0.2: U206.13@-0.2,-37.985 -0.2,-38.767 0,-40.5
  Bottom Layer w0.28: 0,-40.5 0,-41.95 0.75,-42.7 54.15,-42.7 55.05,-43.6 55.05,-44.95 54.15,-45.85 31.25,-45.85 30.325,-46.775 30.325,-48.125 31.275,-49.075 55.075,-49.075 ANT16.2@60,-54
50R_C1: C1.1 L1.1 U1.14 | length 2
  Bottom Layer w0.2: L1.1@65.95,-35.55 L1.1@65.975,-35.55 66.475,-35.55 C1.1@66.5,-35.55 ; U1.14@67.255,-35.55 U1.14@67.238,-35.55 ; C1.1@66.5,-35.55 U1.14@67.238,-35.55 ; C1.1@66.5,-35.55 U1.14@67.238,-35.55
50R_CC1: C2.1 CC1.1 L1.2 | length 1.1
  Bottom Layer w0.2: CC1.1@64.3,-35.55 L1.2@65.375,-35.55
50R_EFR32_RF_OUT: D13.2 R1.2 U201.5 | length 43.2
  Bottom Layer w0.28: R1.2@72.195,-18.597 72.195,-15.13 76.541,-10.784 76.541,-0.466 71.7,4.375 71.7,14.075 73.5,15.875 U201.5@73.5,20.071
50R_HYBRID_IN: H1.1 R208.2 | length 33.2
  Top Layer w0.28: v2(71.443,37.9) 71.443,64.843 v2(71.45,64.85)
  Bottom Layer w0.28: H1.1@67.655,63.746 67.655,64.755 68.225,65.325 70.975,65.325 v2(71.45,64.85) ; R208.2@70.467,37.889 70.479,37.9 v2(71.443,37.9)
50R_HYBRID_OUT_I: CC42.2 R210.2 R211.2 | length 45
  Bottom Layer w0.28: CC42.2@63.638,1.64 65.29,1.64 66.55,2.9 66.55,18.575 64.55,20.575 64.55,40.45 65.55,41.45 R210.2@67.32,41.45
50R_HYBRID_OUT_Q: CC32.2 R212.2 R213.2 | length 41.9
  Top Layer w0.28: v2(74.525,41.45) v2(74.525,70.1)
  Bottom Layer w0.28: CC32.2@66.106,76.507 68.118,76.507 69.769,74.856 69.769,72.856 72.525,70.1 v2(74.525,70.1) ; R212.2@73.52,41.45 v2(74.525,41.45)
50R_P2: P202.1 R2.2 | length 1.7
  Bottom Layer w0.28: R2.2@73.095,-19.497 P202.1@74.795,-19.497
50R_R1: C3.1 CC1.2 R1.1 R2.1 | length 25.5
  Bottom Layer w0.28: C3.1@63.125,-35.45 61.796,-34.121 60.675,-34.121 59.927,-33.373 59.927,-28.523 66.125,-22.325 69.367,-22.325 R2.1@72.195,-19.497 ; C3.1@63.2,-35.55 CC1.2@63.75,-35.55
50R_U101_OUT1: CC11.1 D23.2 U202.5 | length 7.1
  Bottom Layer w0.28: D23.2@73.5,29.455 U202.5@73.5,31.071 ; D23.2@73.524,29.455 73.524,27.268 CC11.1@75.838,24.954
50R_U101_OUT2: CC12.1 R208.1 R209.2 | length 14.1
  Top Layer w0.28: v2(69.567,36.991) 71.813,34.745 v2(71.813,29.206)
  Bottom Layer w0.28: v2(69.567,36.991) R208.1@69.567,37.889 ; CC12.1@71.212,24.974 71.813,25.575 v2(71.813,29.206)
50R_U102_OUT1: CC31.2 D21.2 U202.3 | length 47
  Bottom Layer w0.28: CC31.2@65.92,72.692 71.087,67.525 74.3,67.525 76.65,65.175 76.65,35.129 U202.3@74.45,32.929
50R_U102_OUT2: CC41.2 D22.2 U202.1 | length 47
  Bottom Layer w0.28: CC41.2@66.204,-1.189 68.611,-1.189 70.225,0.425 70.225,2.775 69.1,3.9 69.1,20.125 67.05,22.175 67.05,34.375 68.225,35.55 69.93,35.55 U202.1@72.533,32.947
50R_U103_OUT: C11.2 CC33.1 L11.1 R215.1 | length 85.5
  Bottom Layer w0.28: L11.1@-0.075,39.625 -0.075,62.15 10.557,72.782 55.608,72.782 CC33.1@57.651,74.825
50R_U104_OUT: C21.2 CC43.1 L21.1 R217.1 | length 85.5
  Bottom Layer w0.28: R217.1@3.497,-35.931 48.269,-35.931 64.275,-19.925 64.275,-16.8 57.1,-9.625 57.1,-7.278 CC43.1@58.85,-5.528
BOARD_ID_SCL: TPJ14.1
BOARD_ID_SDA: TPJ15.1
BOARD_ID_WP: TPJ16.1
CP/DP+: U201.6 U203.6 U204.6 U208.4 | length 122.8
  IM3 Signal w0.2: v2(60.178,75.775) 68.975,75.775 72.85,71.9 72.85,68.226 74.551,66.525 74.551,44.474 76.125,42.9 76.125,40 74.53,38.405 74.53,20.884 75.624,19.79 75.624,18.92 v2(75.075,18.371) 74.7,17.996 74.7,11.25 75.425,10.525 ; v2(74.775,-1.45) 74.977,-1.45 74.775,-1.248 74.775,6.25 75.425,6.9 75.425,10.525 ; v2(76.895,8.64) 76.895,9.93 76.3,10.525 75.425,10.525
  IM2 Signal w0.2: v2(58.375,0.45) 70.6,0.45 72.5,-1.45 v2(74.775,-1.45) ; v2(71.395,19.739) 72.763,18.371 v2(75.075,18.371)
  Bottom Layer w0.2: v2(58.375,0.45) 58.375,-0.911 59.987,-2.523 U204.6@60.511,-2.523 ; v2(60.178,75.775) U203.6@60.951,75.775 ; v2(71.395,19.739) 71.726,20.071 U201.6@72.55,20.071 ; U208.4@76.895,7.878 v2(76.895,8.64)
